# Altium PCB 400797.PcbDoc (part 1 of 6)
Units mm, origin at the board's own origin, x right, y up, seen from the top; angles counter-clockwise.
Board outline 155 x 63.5 mm, 4 copper layers (Top Layer, Mid-Layer 1, Mid-Layer 2, Bottom Layer), stack 1.514 mm thick; 317 components, 286 nets, 1519 pads, 2174 vias.
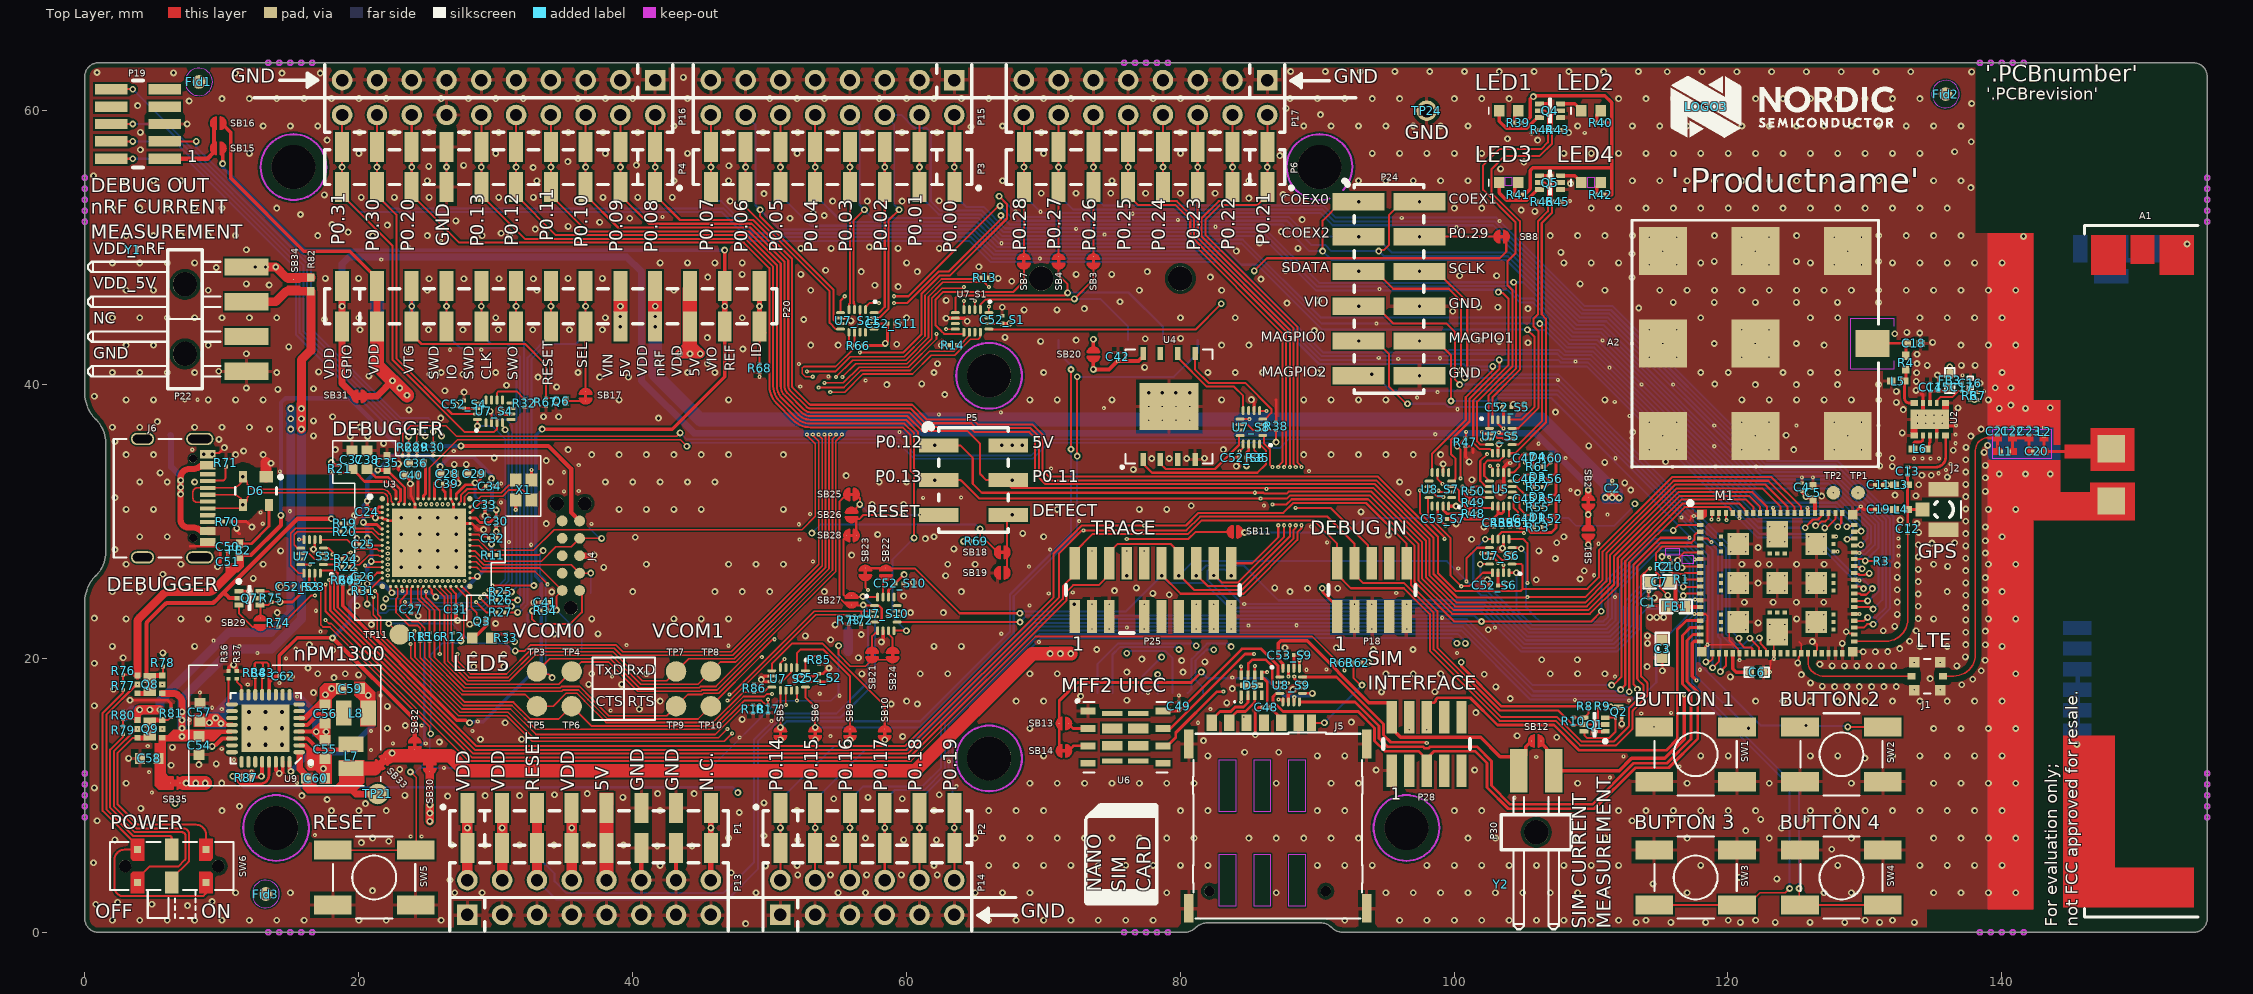
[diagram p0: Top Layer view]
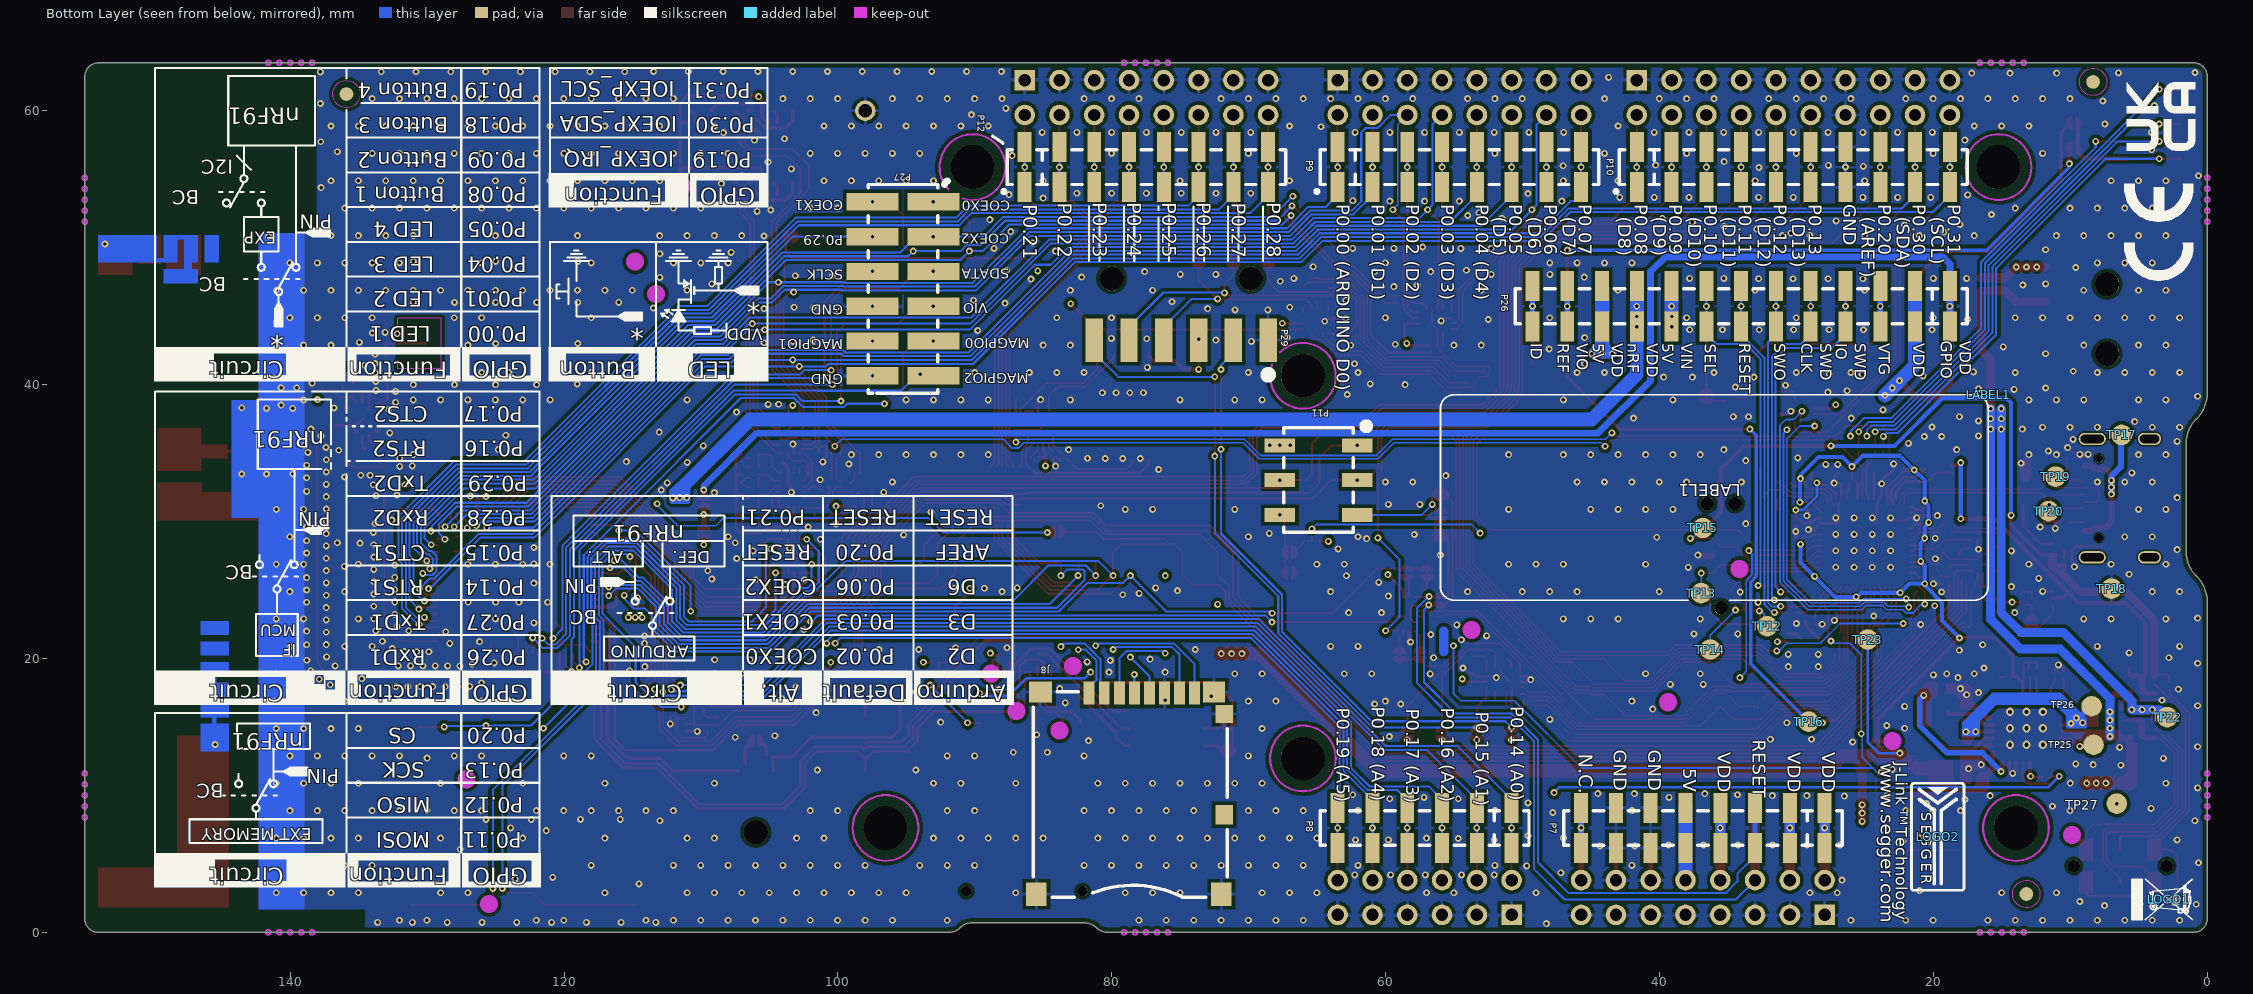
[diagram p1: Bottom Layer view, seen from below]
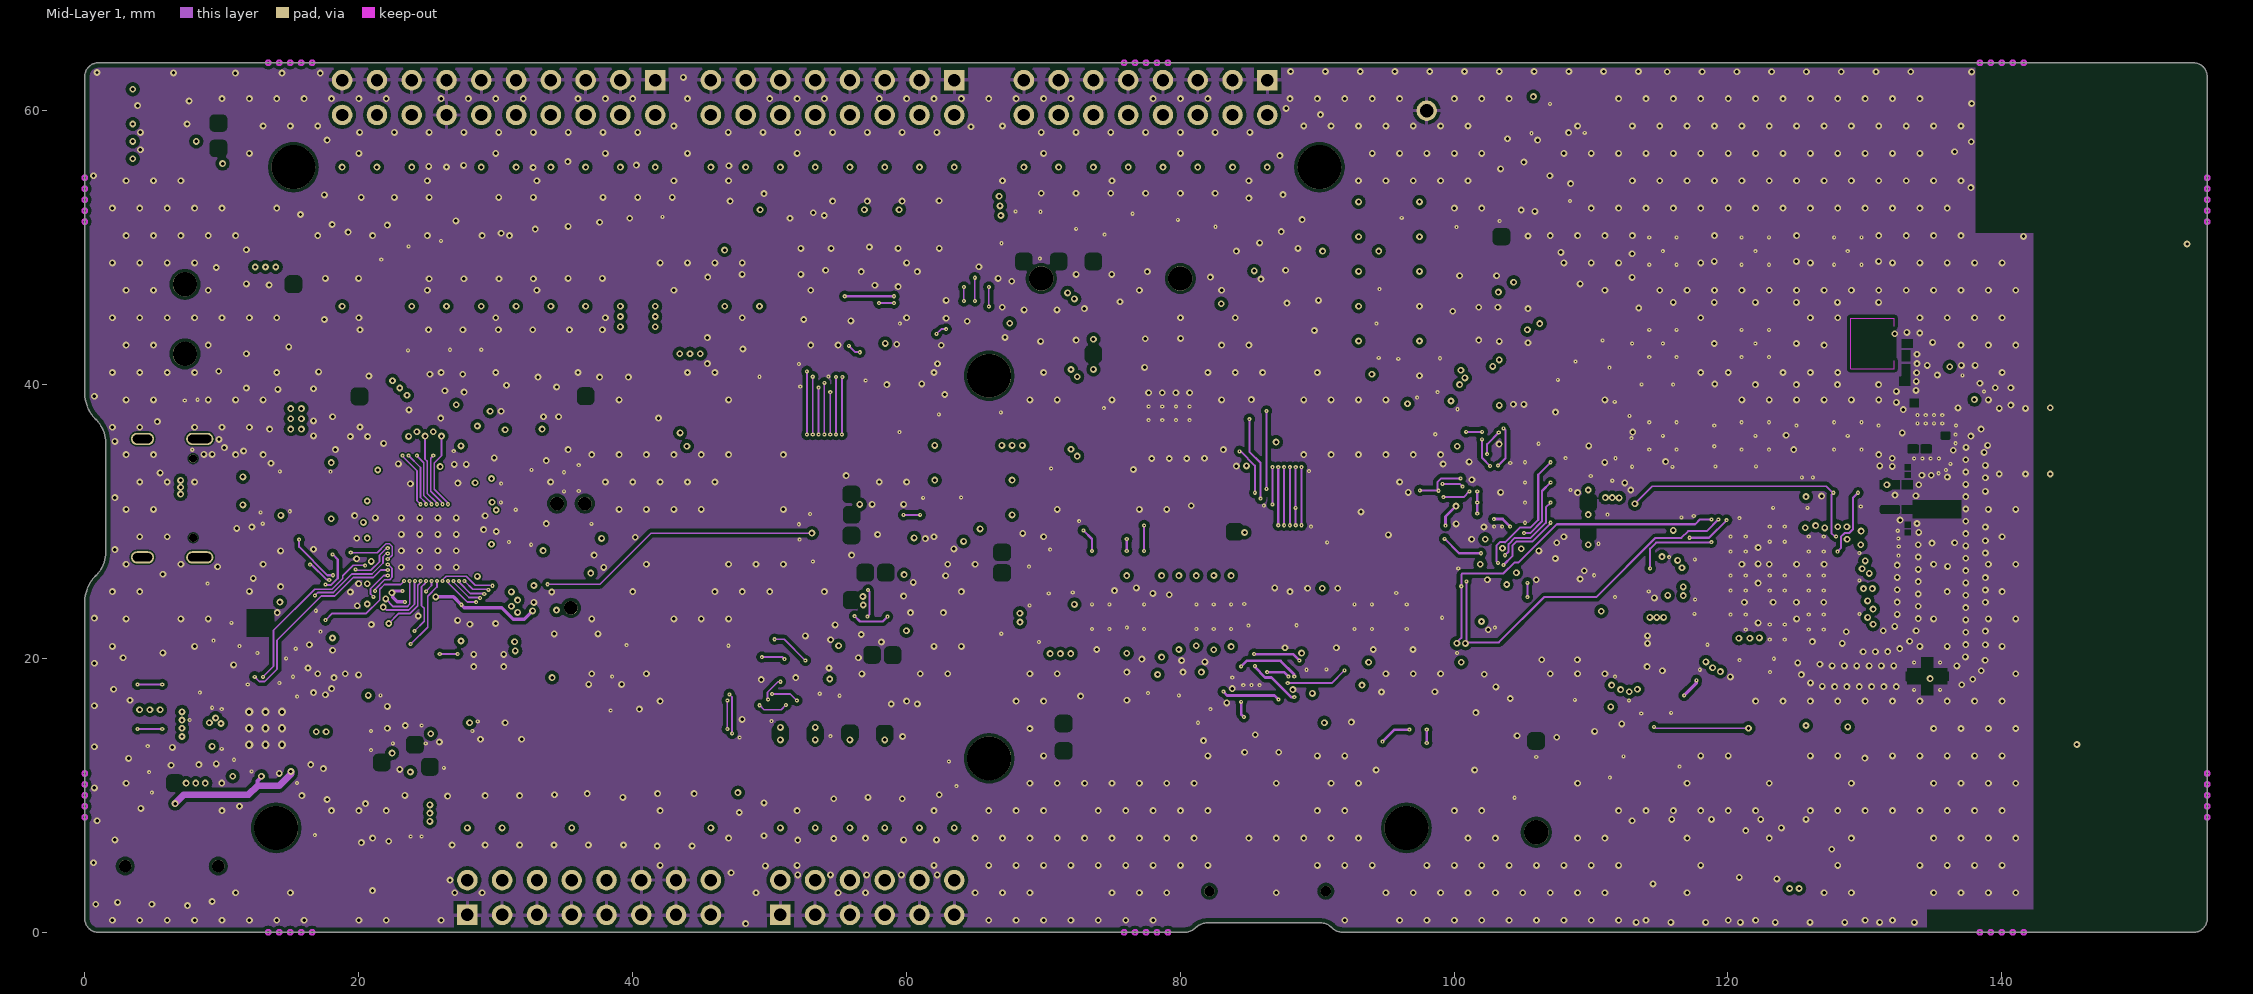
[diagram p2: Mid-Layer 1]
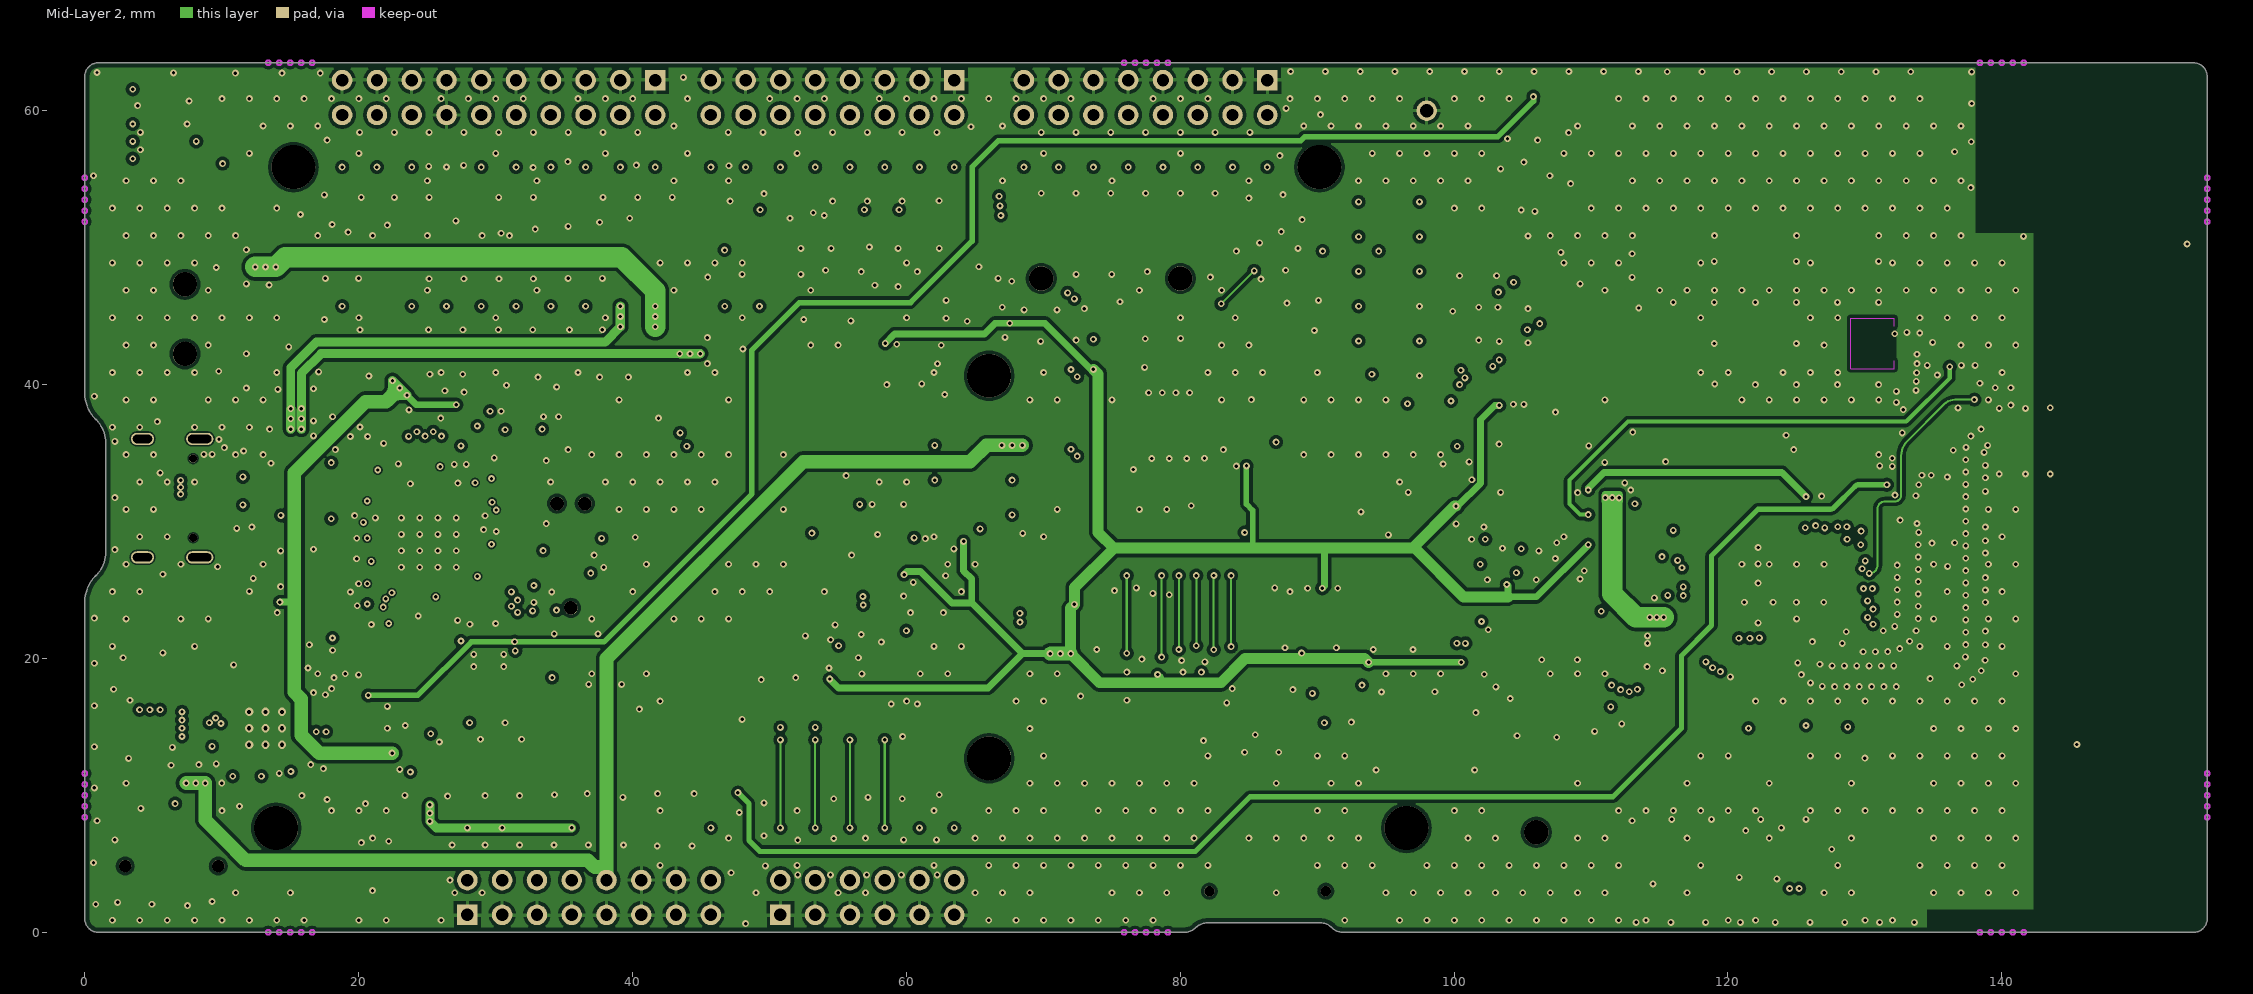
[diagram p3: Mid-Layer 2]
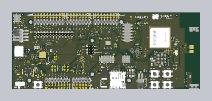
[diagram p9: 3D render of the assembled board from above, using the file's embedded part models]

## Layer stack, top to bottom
Top Solder: solder mask 0.05, Solder Resist Halogen-Free, Dk 3.5
Top Layer: signal copper 0.035
Dielectric1: prepreg 0.072, FR-4 Halogen-Free, Dk 4.18
Mid-Layer 1: signal copper 0.035
Dielectric2: core 1.23, FR-4 Halogen-Free, Dk 4.74
Mid-Layer 2: signal copper 0.035
Dielectric3: prepreg 0.072, FR-4 Halogen-Free, Dk 4.18
Bottom Layer: signal copper 0.035
Bottom Solder: solder mask 0.05, Solder Resist Halogen-Free, Dk 3.5

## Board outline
0,1 0,24.121 cw(c2.717,24.121) 0.796,26.042 0.962,26.208 ccw(c-0.876,27.751) 1.524,27.751 1.524,35.751 ccw(c-0.876,35.751) 0.962,37.294 0.796,37.46 cw(c2.717,39.381) 0,39.381 0,62.5 cw(c1,62.5) 1,63.5 154,63.5 cw(c154,62.5) 155,62.5 155,1 cw(c154,1) 154,0 91.9,0 cw(c91.9,1.18) 91.066,0.346 ccw(c90.231,-0.489) 90.231,0.691 81.969,0.691 ccw(c81.969,-0.489) 81.134,0.346 cw(c80.3,1.18) 80.3,0 1,0 cw(c1,1)

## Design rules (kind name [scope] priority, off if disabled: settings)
BoardOutlineClearance [OnLayer('Top Layer') or OnLayer('Bottom Layer') or OnLayer('Mid-Layer 1') or OnLayer('Mid-Layer 2')] p1: gap=0.35 ignorepadtopadclearanceinfootprint=FALSE
Clearance USB_C [InComponent('J6')] p1: gap=0.1 ignorepadtopadclearanceinfootprint=FALSE
Clearance IMCU_room [WithinRoom('IMCU')] p2: gap=0.1 ignorepadtopadclearanceinfootprint=FALSE
Clearance USB_Poly_Clearance [(InNamedPolygon('Top_Layer-GND')) vs (IsTrack or IsArc) and (InDifferentialPair('D') or InDifferentialPair('USB0'))] p3: gap=1 ignorepadtopadclearanceinfootprint=FALSE
Clearance "NPTH clearance" [Not PadIsPlated And HoleSize > 0] p4: gap=0.23 ignorepadtopadclearanceinfootprint=FALSE
Clearance SB_Clearance [HasFootprint('Solderbridge') or HasFootprint('QFN40P180X140X55-10N')] p5: gap=0.127 ignorepadtopadclearanceinfootprint=FALSE except(0: Arc-Hole Track-Hole SMDPad-Hole THPad-Hole Via-Hole Fill-Hole Poly-Hole Region-Hole Text-Hole)
Clearance CSP_Clearance [HasFootprint('BGA4C40P2X2_76X76X62')] p6: gap=0.127 ignorepadtopadclearanceinfootprint=FALSE except(0: Arc-Hole Track-Hole SMDPad-Hole THPad-Hole Via-Hole Fill-Hole Poly-Hole Region-Hole Text-Hole)
Clearance P23_Clearance [HasFootprint('FPC_05P-0.5mm-RA-SMD')] p7: gap=0.127 ignorepadtopadclearanceinfootprint=FALSE except(0: Arc-Hole Track-Hole SMDPad-Hole THPad-Hole Via-Hole Fill-Hole Poly-Hole Region-Hole Text-Hole)
Clearance PSON35P100X50-8N_Clearance [HasFootprint('PSON35P100X50-8N')] p8: gap=0.15 ignorepadtopadclearanceinfootprint=FALSE except(0: Arc-Hole Track-Hole SMDPad-Hole THPad-Hole Via-Hole Fill-Hole Poly-Hole Region-Hole Text-Hole)
Clearance "Net tie_clearance" [InComponent('NT*') vs IsPad] p9: gap=0.001 ignorepadtopadclearanceinfootprint=TRUE
Clearance Top_layer_Clearance [All vs OnLayer('Top Layer')] p10: gap=0.125 ignorepadtopadclearanceinfootprint=FALSE
Clearance Polygon_Clearance [InNamedPolygon('Top_Layer-GND') or InNamedPolygon('Bottom_Layer-GND') or InNamedPolygon('Mid_Layer_1-GND') or InNamedPolygon('Mid_Layer_2-GND')] p11: gap=0.25 ignorepadtopadclearanceinfootprint=FALSE except(0: Arc-Hole Track-Hole SMDPad-Hole THPad-Hole Via-Hole Fill-Hole Poly-Hole Region-Hole Text-Hole)
Clearance USB_Clearance [InDifferentialPairClass('All Differential Pairs')] p12: gap=0.15 ignorepadtopadclearanceinfootprint=FALSE
Clearance RF_Clerance [InNet('RF') or InNet('ANT')] p13: gap=0.203 ignorepadtopadclearanceinfootprint=FALSE except(0: Arc-Hole Track-Hole SMDPad-Hole THPad-Hole Via-Hole Fill-Hole Poly-Hole Region-Hole Text-Hole)
Clearance [All] p14: gap=0.125 ignorepadtopadclearanceinfootprint=FALSE except(0: Poly-Region Region-Region)
ComponentClearance [All] p1 off: gap=0.254 collisioncheckmode=3 verticalgap=0.254 showdistances=FALSE
DiffPairsRouting [InDifferentialPair('D')] p1: maxlimit=0.15 minlimit=0.127 mostfreqgap=0.15 toplayer_mingap=0.15 toplayer_minwidth=0.1 toplayer_maxwidth=0.1 toplayer_prefwidth=0.1 midlayer1_maxgap=0.127 midlayer1_prefgap=0.127 midlayer1_minwidth=0.054 midlayer1_maxwidth=0.054 midlayer1_prefwidth=0.054 midlayer2_maxgap=0.127 midlayer2_prefgap=0.127 midlayer2_minwidth=0.054 midlayer2_maxwidth=0.054 midlayer2_prefwidth=0.054 bottomlayer_mingap=0.15 bottomlayer_minwidth=0.1 bottomlayer_maxwidth=0.1 bottomlayer_prefwidth=0.1 impedanceprofiledriven=TRUE impedanceprofileid={5F1D737F-A6A0-4321-8E3C-81C77A155CAF} impedanceprofilevalue=90.000000 maxuncoupledlength=12.7
FabricationTestPointUsage TestPointUsage [All] p1: valid=0 allowmultiple=FALSE
FabricationTestpoint Testpoint [All] p1: side=3 testpointundercomponent=TRUE minsize=1.016 maxsize=2.54 preferedsize=1.524 minholesize=0 maxholesize=1.016 preferedholesize=0.813 testpointgrid=0.025 allowsidetop=TRUE allowsidebottom=TRUE usegrid=TRUE gridtolerance=0
Height [All] p1 off: minheight=0 maxheight=25.4 prefheight=12.7
HoleSize [All] p1: absolutevalues=TRUE maxlimit=5 minlimit=0.1 maxpercent=80.000 minpercent=20.000
HoleToHoleClearance [All] p1: gap=0.25 allowstackedmicrovias=FALSE
MinimumAnnularRing [All] p1 off: minimumring=0.152
MinimumSolderMaskSliver USB-C [HasFootprint('SD-80259-001')] p1: minsoldermaskwidth=0
MinimumSolderMaskSliver PMIC [WithinRoom('nPM1300')] p2: minsoldermaskwidth=0
MinimumSolderMaskSliver [All] p3: minsoldermaskwidth=0.05
NetAntennae NetAntennae_ANT [InNet('ANT')] p1: netantennaetolerance=40
NetAntennae [All] p2: netantennaetolerance=0
PlaneClearance [All] p1: clearance=0.25
PlaneConnect [All] p1: planeconnectstyle=Direct reliefexpansion=0.508 reliefentries=4 reliefconductorwidth=0.254 reliefairgap=0.254
PolygonConnect VDD_nRF [InNet('VDD_nRF')] p1: connectstyle=Direct reliefconductorwidth=0.254 reliefentries=4 polygonreliefangle="90 Angle" airgapwidth=0.254
PolygonConnect VCC_and_VDD [InNet('NetC50_2')] p2: connectstyle=Direct reliefconductorwidth=0.254 reliefentries=4 polygonreliefangle="90 Angle" airgapwidth=0.254
PolygonConnect GND_Poly [isVia and innet(gnd) or isVia and innet('VDD') or HasFootprint('COAXIAL-SWF') or isVia and innet('VDD_SAM') or InComponent('R80') or HasFootprint('COAXIAL RF U.FL-R-SMT-1') or HasFootprint('DSGP.1575.18') or HasFootprint('DX07S016JA1R1500')] p3: connectstyle=Direct reliefconductorwidth=0.254 reliefentries=4 polygonreliefangle="90 Angle" airgapwidth=0.254
PolygonConnect General [All] p4: connectstyle=Relief reliefconductorwidth=0.254 reliefentries=4 polygonreliefangle="90 Angle" airgapwidth=0.254
RoomDefinition IMCU [InComponentClass('IMCU') vs False] p1: confinementstyle=ConfineIn formatcopy=TRUE lockcomponents=FALSE outline 18.089,33.044 18.089,34.657 18.67,34.657 18.67,36.019 21.455,36.019 21.455,35.514 22.755,35.514 22.755,34.944 25.405,34.944 25.405,34.164 27.705,34.164 29.68,34.164 29.68,33.844 33.38,33.844 33.38,30.783 30.586,30.783 30.586,29.228 30.582,29.228 30.582,28.248 28.954,28.248 28.954,24.43 27.636,24.43 27.636,22.778 24.279,22.778 24.279,20.471 21.721,20.471 21.721,24.43 20.321,24.43 20.321,25.423 19.543,25.423 19.543,27.798 19.543,33.009 18.67,33.009 18.67,33.044
RoomDefinition nPM1300 [InComponentClass('nPM1300') vs False] p2: confinementstyle=ConfineIn formatcopy=TRUE lockcomponents=FALSE outline 5.325,8.12 5.325,10.678 7.021,10.678 7.021,17.679 9.846,17.679 9.846,18.254 9.966,18.254 9.966,19.604 19.196,19.604 19.196,39.954 21.104,39.954 21.104,22.659 26.074,22.659 26.074,20.101 26.049,20.101 26.049,11.145 22.974,11.145 22.974,11.124 22.654,11.124 22.654,8.846 7.883,8.846 7.883,8.12
RoutingVias [All] p1: holewidth=0.25 width=0.5 viastyle="Through Hole" minholewidth=0.1 minwidth=0.3 maxholewidth=0.305 maxwidth=0.61
ShortCircuit "PVSS and GND" [InNet('PVSS1') or InNet('PVSS2') vs InNet('GND')] p1: allowed=TRUE
ShortCircuit ShortCircuit_1 [HasFootprint('P822601')] p2: allowed=TRUE
ShortCircuit [All] p3: allowed=FALSE
SilkToSilkClearance [All] p1: silktosilkclearance=0.15
SilkToSolderMaskClearance SilkscreenOverComponentPads [IsPad] p1: minsilkscreentomaskgap=0.254 clearancetoexposedcopper=TRUE
SolderMaskExpansion SolderMaskExpansion_Via [IsVia] p1: expansion=0.102 istentingtop=TRUE
SolderMaskExpansion SolderMaskExpansion_USB [HasFootprint('L-KLS1-5473')] p2: expansion=0.06 istentingtop=FALSE
SolderMaskExpansion [All] p3: expansion=0.076 istentingtop=FALSE
UnpouredPolygon [All] p1 off:
Width Width_RF [InNet('ANT') or InNet('LTE_RF1') or InNet('GPS_RF1')] p1: maxlimit=0.254 minlimit=0.1 preferedwidth=0.254 toplayer_maxwidth=0.1 toplayer_prefwidth=0.1 bottomlayer_maxwidth=0.1 bottomlayer_prefwidth=0.1 impedanceprofiledriven=TRUE impedanceprofileid={28F3A609-7DB3-45B1-BB45-39A827C1017D} impedanceprofilevalue=50.000000 minimp=50.000000 maximp=50.000000 favimp=50.000000
Width Width_Diff [(InDifferentialPairClass('All Differential Pairs'))] p2: maxlimit=0.165 minlimit=0.1 preferedwidth=0.165
Width Width_GPIO [InNetClass('GPIO')] p3: maxlimit=0.152 minlimit=0.125 preferedwidth=0.15 minimp=50.000000 maximp=50.000000 favimp=50.000000
Width Width_GPIO_1 [InNetClass('COEX')] p4: maxlimit=0.152 minlimit=0.125 preferedwidth=0.15 minimp=50.000000 maximp=50.000000 favimp=50.000000
Width Width_GPIO_2 [InNetClass('SWD')] p5: maxlimit=0.152 minlimit=0.125 preferedwidth=0.15 minimp=50.000000 maximp=50.000000 favimp=50.000000
Width Width_GPIO_3 [InNetClass('UART')] p6: maxlimit=0.152 minlimit=0.125 preferedwidth=0.15 minimp=50.000000 maximp=50.000000 favimp=50.000000
Width [All] p7: maxlimit=2.54 minlimit=0.125 preferedwidth=0.15
15 further rules are at their usual default settings.

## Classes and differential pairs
net class VCOM: VCOM0_CTRL VCOM0_CTS VCOM0_HWFC VCOM0_RTS VCOM0_RXD VCOM0_TXD VCOM1_CTRL VCOM1_CTS VCOM1_HWFC VCOM1_RTS VCOM1_RXD VCOM1_TXD
net class nRF9151_UART: P0.14/AIN1 P0.15/AIN2 P0.16/AIN3 P0.17/AIN4 P0.26 P0.27 P0.28 P0.29
net class EXT_MEM: P0.11 P0.12 P0.13/AIN0 P0.20/AIN7
component class IMCU: C24 C25 C26 C27 C28 C29 C30 C31 C32 C33 C34 C35 C36 C37 C38 C39 C40 R21 TP11 U3 X1
component class nPM1300: C54 C55 C56 C57 C59 C60 C62 L7 L8 R36 R37 R87 SB30 SB31 SB32 SB33 TP21 TP23 TP25 TP26 TP27 U9
net class RF: ANT GPS_RF1 GPS_RF2 GPS_RF3 GPS_RF4 GPS_RF5 LTE_RF1 NetA1_1 NetC20_1
channel class pca10171_switch_nx: S7 S9
channel class pca10171_switch_fsa: S1 S2 S3 S4 S5 S6 S8 S10 S11
net class SWD: P0.22 RESET SWD0_CLK SWD0_IO SWD0_RESET SWD0_SEL SWD0_SWO SWD1_CLK SWD1_IO SWD1_RESET SWD1_SEL SWD1_SWO SWD3_CLK SWD3_IO SWD3_RESET SWD3_SWO SWD_CTRL SWDCLK SWDIO
net class COEX: COEX0 COEX1 COEX2 MAGPIO0 MAGPIO1 MAGPIO2 MIPI_SCLK MIPI_SDATA MIPI_VIO
net class GPIO: AREF BTN1_EXT BTN2_EXT BTN3_EXT BTN4_EXT BUTTON1 BUTTON2 BUTTON3 BUTTON4 COEX0 COEX1 COEX2 COEX_SELECT COM.CH1_S1 COM.CH2_S2 COM.CH3_S1 COM.CH4_S2 EXT_MEM_C\S\ EXT_MEM_CTRL EXT_MEM_MISO EXT_MEM_MOSI EXT_MEM_SCK IMCU_LED IMCU_SCL IMCU_SDA INT_EXT IOEXP_CTRL LED1 LED1_EXT LED2 LED2_EXT LED3 LED3_EXT LED4 LED4_EXT MAGPIO0 MAGPIO1 MAGPIO2 MIPI_SCLK MIPI_SDATA MIPI_VIO NC.CH1_S3 NC.CH3_S3 NC.CH4_S3 NetC44_1 NetC45_2 NetC46_2 NetC47_2 NetR51_1 NetR58_1 NO.CH1_S8 P0.00 P0.01 P0.02 P0.03 P0.04 P0.05 P0.06 P0.07 P0.08 P0.09 P0.10 P0.11 P0.12 P0.13/AIN0 P0.14/AIN1 P0.15/AIN2 P0.16/AIN3 P0.17/AIN4 P0.18/AIN5 P0.19/AIN6 P0.20/AIN7 P0.21 P0.22 P0.23 P0.24 P0.25 P0.26 P0.27 P0.28 P0.29 P0.30 P0.31 RESET RESET_BUTTON RESET_IN_CTRL RESET_OUT_CTRL SCL_EXT SDA_EXT SHIELD_DETECT SIM_SELECT SWD0_CLK SWD0_IO SWD0_RESET SWD0_SEL SWD0_SWO SWD1_CLK SWD1_IO SWD1_RESET SWD1_SEL SWD1_SWO SWD3_CLK SWD3_IO SWD3_RESET SWD3_SWO SWD_CTRL SWDCLK SWDIO TGT_SCL TGT_SDA TGT_TWI_CTRL UART1.CTS UART1.RTS UART1.RXD UART1.TXD UART2.CTS UART2.RTS UART2.RXD UART2.TXD USB_DETECT VCOM0_CTRL VCOM0_CTS VCOM0_HWFC VCOM0_RTS VCOM0_RXD VCOM0_TXD VCOM1_CTRL VCOM1_CTS VCOM1_HWFC VCOM1_RTS VCOM1_RXD VCOM1_TXD VIO_REF_SENSE
differential pair D: +D_P -D_N

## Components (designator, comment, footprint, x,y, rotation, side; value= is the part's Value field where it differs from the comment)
A1 "P822601" P822601 150.28,26.417 r270 top
A2 "DSGP.1575.18" DSGP.1575.18.4.C.02 122,43 r90 top
C1 "1.0µF" CAPC0603X03L_C 114.19,24.1 r90 top value=1.0ÂµF
C2 "1.0µF" CAPC0603X03L_C 111.55,32.425 r90 top value=1.0ÂµF
C3 "10µF" CAPC1608X06L 115.2,20.7 r270 top value=10ÂµF
C4 "100nF" CAPC0603X03L_C 125.4,32.5 r90 top
C5 "4.7µF" CAPC1005X04L 126.2,32.1 r90 top value=4.7ÂµF
C6 "4.7µF" CAPC1005X04L 122.1,19 r0 top value=4.7ÂµF
C7 "10µF" CAPC1608X06L 115,25.6 r180 top value=10ÂµF
C10 "100nF" CAPC0603X03L_C 115.8,26.7 r90 top
C11 "39pF" CAPC0603X03L_C 131.03,32.68 r0 top
C12 "39pF" CAPC0603X03L_C 133.13,29.48 r270 top
C13 "39pF" CAPC0603X03L_C 133.13,33.682 r270 top
C14 "100pF" CAPC0603X03L_C 134.8,39.822 r270 top
C15 "100nF" CAPC0603X03L_C 135.375,39.822 r270 top
C16 "100nF" CAPC0603X03L_C 137.7,40.1 r270 top
C17 "100pF" CAPC0603X03L_C 137.1,39.8 r270 top
C18 "N.C." CAPC1005X04L_NC 133.575,43 r0 top
C19 "N.C." CAPC0603X03L_C_NC 131.03,30.88 r0 top
C20 "3.5pF" CAPC0603X03L_C 142.545,35.117 r0 top
C21 "N.C." CAPC0603X03L_C_NC 139.7,36.577 r270 top
C22 "N.C." CAPC0603X03L_C_NC 140.784,36.577 r270 top
C23 "N.C." CAPC0603X03L_C_NC 141.986,36.577 r270 top
C24 "100nF" CAPC0603X03L_C 20.625,30.709 r90 top
C25 "100nF" CAPC0603X03L_C 20.35,28.334 r0 top
C26 "100nF" CAPC0603X03L_C 20.35,25.959 r180 top
C27 "100nF" CAPC0603X03L_C 23.827,23.584 r90 top
C28 "1.0µF" CAPC1005X04L 26.475,33.484 r0 top value=1.0ÂµF
C29 "1.0µF" CAPC1005X04L 28.45,33.484 r0 top value=1.0ÂµF
C30 "2.2nF" CAPC0603X03L_C 30.05,30.034 r270 top
C31 "100nF" CAPC0603X03L_C 27.1,23.584 r90 top
C32 "100nF" CAPC0603X03L_C 29.775,28.784 r180 top
C33 "100nF" CAPC0603X03L_C 29.225,31.234 r90 top
C34 "100nF" CAPC0603X03L_C 29.575,32.575 r0 top
C35 "1.0µF" CAPC1005X04L 22.075,34.284 r270 top value=1.0ÂµF
C36 "1.0µF" CAPC1005X04L 24.175,34.264 r0 top value=1.0ÂµF
C37 "4.7µF" CAPC1608X06L 19.5,34.514 r90 top value=4.7ÂµF
C38 "4.7µF" CAPC1608X06L 20.625,34.514 r90 top value=4.7ÂµF
C39 "100nF" CAPC0603X03L_C 26.444,32.759 r0 top
C40 "1.0µF" CAPC1005X04L 23.825,33.389 r0 top value=1.0ÂµF
C41 "10nF" CAPC0603X03L_C 33.625,24.1 r0 top
C42 "100nF" CAPC0603X03L_C 75.45,42.05 r270 top
C43 "100nF" CAPC0603X03L_C 102.927,29.912 r90 top
C44 "1.0µF" CAPC0603X03L_C 105.174,30.191 r270 top value=1.0ÂµF
C45 "1.0µF" CAPC0603X03L_C 105.174,31.664 r90 top value=1.0ÂµF
C46 "1.0µF" CAPC0603X03L_C 105.174,33.137 r90 top value=1.0ÂµF
C47 "1.0µF" CAPC0603X03L_C 105.174,34.611 r90 top value=1.0ÂµF
C48 "10nF" CAPC0603X03L_C 86.275,16.425 r180 top
C49 "N.C." CAPC0603X03L_C_NC 79.9,16.5 r270 top
C50 "10nF" CAPC0603X03L_C 10.425,28.15 r90 top
C51 "100nF" CAPC0603X03L_C 10.425,27.05 r270 top
C52_S1 "100nF" CAPC0603X03L_C 67,44.75 r90 top (schematic designator C52)
C52_S2 "100nF" CAPC0603X03L_C 53.625,18.6 r90 top (schematic designator C52)
C52_S3 "100nF" CAPC0603X03L_C 15.55,25.25 r180 top (schematic designator C52)
C52_S4 "100nF" CAPC0603X03L_C 27.7,38.55 r90 top (schematic designator C52)
C52_S5 "100nF" CAPC0603X03L_C 103.898,38.359 r0 top (schematic designator C52)
C52_S6 "100nF" CAPC0603X03L_C 102.923,25.334 r180 top (schematic designator C52)
C52_S8 "100nF" CAPC0603X03L_C 84.553,34.671 r180 top (schematic designator C52)
C52_S10 "100nF" CAPC0603X03L_C 59.5,25.475 r0 top (schematic designator C52)
C52_S11 "100nF" CAPC0603X03L_C 58.9,44.45 r0 top (schematic designator C52)
C53_S7 "100nF" CAPC0603X03L_C 99.197,30.192 r0 top (schematic designator C53)
C53_S9 "100nF" CAPC0603X03L_C 88,20.25 r180 top (schematic designator C53)
C54 "1.0µF" CAPC1608X06L 8.35,13.65 r90 top value=1.0ÂµF
C55 "10µF" CAPC1608X06L 17.55,13.35 r90 top value=10ÂµF
C56 "10µF" CAPC1608X06L 17.55,15.95 r270 top value=10ÂµF
C57 "10µF" CAPC1608X06L 8.4,16.075 r270 top value=10ÂµF
C58 "4.7µF" CAPC1608X06L 4.7,12.7 r0 top value=4.7ÂµF
C59 "10µF" CAPC1608X06L 19.4,17.8 r0 top value=10ÂµF
C60 "10µF" CAPC1608X06L 16.85,11.25 r180 top value=10ÂµF
C62 "100nF" CAPC0603X03L_C 14.5,18.7 r0 top
D1 "CFSH05-20L" SODFL35X40-2N 106.114,30.318 r180 top
D2 "CFSH05-20L" SODFL35X40-2N 106.114,31.791 r180 top
D3 "CFSH05-20L" SODFL35X40-2N 106.114,33.264 r180 top
D4 "CFSH05-20L" SODFL35X40-2N 106.114,34.738 r180 top
D5 "TPD3F303DPVR" SON50P210X160X65_HS-9N 85.2,18.05 r90 top
D6 "PRTR5V0U2X" SOT190P230X110-4L 12.497,32.234 r270 top
FB1 "22R@100M/6A" INDC1608X06L 116.2,23.8 r0 top
FB2 "120R/0.55A" INDC1005X04L 11.3,27.9 r270 top
FB3 "120R/1.2A" INDC1005X04L 136.2,40.3 r90 top
Fid1 "Fiducial mark" Fiducial 8.335,62.104 r0 top value=N.A.
Fid2 "Fiducial mark" Fiducial 135.89,61.214 r0 top value=N.A.
Fid3 "Fiducial mark" Fiducial 13.208,2.795 r0 top value=N.A.
J1 "MM8130-2600" COAXIAL-SWF 134.554,18.7 r90 top
J2 "MHF I Receptacle" "COAXIAL RF U.FL-R-SMT-1" 135.73,30.88 r270 top
J4 "TC2050-IDC" TC2050-IDC-NLFP 35.5,27.5 r90 top
J5 "KLS1-SIM-066" KLS1-SIM-066 82.3,15.3 r0 top
J6 "USB-C 2.0" SD-80259-001 6.6,31.705 r270 top
J8 "microSD Card Connector" Molex_502774-0891 72.75,17.55 r0 bottom
L1 "1.5nH" INDC0603X03L_C 140.233,35.117 r0 top
L2 "22nH" INDC0603X03L_C 143.084,36.573 r270 top
L3 "68nH" INDC1005X04L_WW 132.63,32.68 r0 top
L4 "N.C." INDC1005X04L_NC 132.63,30.88 r180 top
L5 "N.C." INDC1005X04L_NC 132.4,40.25 r180 top
L6 "9.1nH" INDC1005X04L_WW 134,35.3 r180 top
L7 "2.2µH" INDC2016X10N 19.45,12.85 r90 top value=2.2ÂµH
L8 "2.2µH" INDC2016X10N 19.8,16 r180 top value=2.2ÂµH
LABEL1 "15x40mm" LabelSilk_15x40 16,39.251 r0 bottom
LED1 "L0603G" LED_0603_G 104,60 r0 top
LED2 "L0603G" LED_0603_G 110,60 r0 top
LED3 "L0603G" LED_0603_G 104,54.75 r0 top
LED4 "L0603G" LED_0603_G 110,54.75 r0 top
LED5 "L0603G" LED_0603_G 29,21.5 r0 top
LOGO1 "WEE Symbol" WEE_3x4.5mm 2.8,2.4 r270 bottom
LOGO2 "Segger Logo S" SEGGER_LOGO_S 19.675,6.975 r270 bottom
LOGO3 "Nordic Logo" NORDIC_LOGO_LYING 118.4,60.275 r0 top
M1 "nRF9151-LACAA0A" LGA50P1210X1110X130-113N 123.6,25.5 r270 top
P1 "Socket 1x8" SOCKET_1x8_SMD 27.94,7.621 r0 top
P2 "Socket 1x6" SOCKET_1x6_SMD 50.8,7.621 r0 top
P3 "Socket 1x8" SOCKET_1x8_SMD 63.5,55.881 r180 top
P4 "Socket 1x10" SOCKET_1x10_SMD 41.656,55.881 r180 top
P5 "Pin Hdr 2x3" HDR_2x3-SMD 64.897,33.021 r270 top
P6 "Socket 1x8" SOCKET_1x8_SMD 86.36,55.881 r180 top
P7 "Pin List 1x8" LIST_1x8_SMD-NC 27.94,7.621 r0 bottom
P8 "Pin List 1x6" LIST_1x6_SMD-NC 50.8,7.621 r0 bottom
P9 "Pin List 1x8" LIST_1x8_SMD-NC 63.5,55.881 r180 bottom
P10 "Pin List 1x10" LIST_1x10_SMD-NC 41.656,55.881 r180 bottom
P11 "Socket 2x3" SOCKET_2x3_SMD-2.54mm-bottom-NC 64.897,33.021 r270 top
P12 "Pin List 1x8" LIST_1x8_SMD-NC 86.36,55.881 r180 bottom
P13 "Pin Header 2x8" HDR_2x8-NC 36.83,2.541 r0 top
P14 "Pin Header 2x6" HDR_2x6-NC 57.15,2.541 r0 top
P15 "Pin Header 2x8" HDR_2x8-NC 54.61,60.961 r180 top
P16 "Pin Header 2x10" HDR_2x10-NC 30.226,60.961 r180 top
P17 "Pin Header 2x8" HDR_2x8-NC 77.47,60.961 r180 top
P18 "Pin Header 2x5, 1.27mm" HDR_2x5-SMD-1.27mm-K 94,25 r0 top
P19 "Pin Header 2x5, 1.27mm" HDR_2x5-SMD-1.27mm-K 3.886,59.031 r90 top
P20 "Pin List 1x13" LIST_1x13_SMD 18.796,45.721 r0 top
P22 "Pin List 1x4, Angled" LIST_ANG_1x4-SMD-2.54MM 11.811,44.779 r270 top
P24 "Socket 2x6" SOCKET_2x6_SMD-2.54mm#1 95.25,46.991 r270 top
P25 "Pin Header 2x10, 1.27mm, SWD" HDR_2x10-SMD-1.27mm-K-SWD 78,25 r0 top
P26 "Socket 1x13" LIST_1x13_SMD-NC 18.796,45.721 r0 bottom
P27 "Socket 2x6" SOCKET_2x6_SMD-2.54mm#2 95.25,46.991 r270 bottom
P28 "Pin Header 2x5, 1.27mm" HDR_2x5-SMD-1.27mm 98,13.75 r0 top
P29 "Pin List 1x6, Angled" LIST_ANG_1x6-SMD-2.54MM 74.93,43.25 r0 bottom
P30 "Pin List 1x2, Angled" LIST_ANG_1x2-SMD-2.54MM 106,11.8 r0 top
Q1 "DMC2400UV" SOTFL50P162X60-6N 110.265,15.175 r180 top
Q2 "RV2C010UNT2L" DFN65P100X40-3L 112.015,16.1 r90 top
Q3 "RV2C010UNT2L" DFN65P100X40-3L 28.975,22.725 r0 top
Q4 "UM6X1NA" SOTFL50P162X60-6N 107,60 r180 top
Q5 "UM6X1NA" SOTFL50P162X60-6N 107,54.75 r180 top
Q6 "RV2C010UNT2L" DFN65P100X40-3L 34.775,38.8 r0 top
Q7 "DMC2400UV" SOTFL50P162X60-6N 12.025,24.4 r0 top
Q8 "MCM2301" DFN65P200X200X80_HS-6N 4.75,18.1 r0 top
Q9 "MCM2301" DFN65P200X200X80_HS-6N 4.75,14.85 r0 top
R1 "10k" RESC0603X03L_C 116.6,25.8 r0 top
R2 "1k" RESC0603X03L_C 115.2,26.7 r270 top
R3 "1M0" RESC0603X03L_C 131.2,27.1 r180 top
R4 "0R" RESC1005X04L 133,41.6 r90 top
R6 "1k" RESC0603X03L_C 137.675,39.172 r90 top
R7 "1M0" RESC0603X03L_C 138.25,39.172 r270 top
R8 "10k" RESC0603X03L_C 109.54,16.5 r0 top
R9 "N.C." RESC0603X03L_C_NC 110.815,16.5 r0 top
R10 "100k" RESC0603X03L_C 108.715,15.4 r90 top
R11 "150R" RESC0603X03L_C 29.775,27.55 r0 top
R12 "150R" RESC0603X03L_C 26.85,21.584 r270 top
R13 "1M0" RESC0603X03L_C 65.725,47.8 r0 top
R14 "1M0" RESC0603X03L_C 63.4,42.875 r0 top
R15 "150R" RESC0603X03L_C 24.5,21.584 r270 top
R16 "150R" RESC0603X03L_C 25.175,21.584 r270 top
R17 "1M0" RESC0603X03L_C 49.9,16.3 r270 top
R18 "1M0" RESC0603X03L_C 48.8,16.3 r90 top
R19 "150R" RESC0603X03L_C 18.975,29.859 r180 top
R20 "150R" RESC0603X03L_C 18.975,29.259 r180 top
R21 "2R2" RESC0603X03L_C 18.625,33.85 r270 top
R22 "150R" RESC0603X03L_C 19.075,26.684 r180 top
R23 "N.C." RESC0603X03L_C_NC 16.675,25.25 r180 top
R24 "1M0" RESC0603X03L_C 19.075,27.275 r180 top
R25 "150R" RESC0603X03L_C 30.375,24.859 r0 top
R26 "150R" RESC0603X03L_C 30.375,24.259 r0 top
R27 "150R" RESC0603X03L_C 30.375,23.359 r0 top
R28 "150R" RESC0603X03L_C 23.65,35.409 r90 top
R29 "150R" RESC0603X03L_C 24.25,35.409 r90 top
R30 "150R" RESC0603X03L_C 25.45,35.409 r90 top
R31 "1M0" RESC0603X03L_C 20.35,24.925 r180 top
R32 "1M0" RESC0603X03L_C 32.1,38.65 r90 top
R33 "120R" RESC0603X03L_C 30.75,21.5 r270 top
R34 "100k" RESC0603X03L_C 33.625,23.5 r180 top
R35 "100k" RESC0603X03L_C 85.653,34.671 r180 top
R36 "47k" RESC0603X03L_C 10.5,18.8 r90 top
R37 "150k" RESC0603X03L_C 11.1,18.8 r90 top
R38 "1M0" RESC0603X03L_C 87.003,36.946 r270 top
R39 "120R" RESC0603X03L_C 104.699,59.118 r0 top
R40 "120R" RESC0603X03L_C 110.699,59.118 r0 top
R41 "120R" RESC0603X03L_C 104.699,53.868 r0 top
R42 "120R" RESC0603X03L_C 110.699,53.868 r0 top
R43 "1M0" RESC0603X03L_C 107.574,58.6 r180 top
R44 "1M0" RESC0603X03L_C 106.456,58.6 r0 top
R45 "1M0" RESC0603X03L_C 107.563,53.35 r180 top
R46 "1M0" RESC0603X03L_C 106.445,53.35 r0 top
R47 "1M0" RESC0603X03L_C 100.825,35.775 r90 top
R48 "4k7" RESC0603X03L_C 101.403,30.572 r0 top
R49 "4k7" RESC0603X03L_C 101.403,31.385 r0 top
R50 "12k" RESC0603X03L_C 101.403,32.198 r0 top
R51 "12k" RESC0603X03L_C 104.68,29.912 r270 top
R52 "100k" RESC0603X03L_C 107.048,30.191 r90 top
R53 "18k" RESC0603X03L_C 106.114,29.581 r0 top
R54 "100k" RESC0603X03L_C 107.048,31.664 r90 top
R55 "18k" RESC0603X03L_C 106.114,31.055 r0 top
R56 "100k" RESC0603X03L_C 107.048,33.137 r90 top
R57 "18k" RESC0603X03L_C 106.114,32.528 r0 top
R58 "0R" RESC0603X03L_C 104.095,29.912 r270 top
R59 "N.C." RESC0603X03L_C_NC 103.511,29.912 r90 top
R60 "100k" RESC0603X03L_C 107.048,34.611 r90 top
R61 "18k" RESC0603X03L_C 106.114,34.001 r0 top
R62 "1M0" RESC0603X03L_C 92.95,19.7 r180 top
R63 "100k" RESC0603X03L_C 91.8,19.7 r0 top
R64 "100k" RESC0603X03L_C 18.825,25.7 r90 top
R65 "100k" RESC0603X03L_C 19.4,25.7 r90 top
R66 "1M0" RESC0603X03L_C 56.5,42.85 r180 top
R67 "1M0" RESC0603X03L_C 33.675,38.7 r270 top
R68 "1k87" RESC0603X03L_C 49.276,41.175 r90 top
R69 "1M0" RESC0603X03L_C 65.1,28.55 r180 top
R70 "5k1" RESC0603X03L_C 10.4,30 r180 top
R71 "5k1" RESC0603X03L_C 10.3,34.3 r270 top
R72 "1M0" RESC0603X03L_C 56.7,22.8 r270 top
R73 "1M0" RESC0603X03L_C 55.775,22.8 r90 top
R74 "47k" RESC0603X03L_C 14.125,22.6 r270 top
R75 "1M0" RESC0603X03L_C 13.625,24.4 r90 top
R76 "100k" RESC0603X03L_C 2.8,19.1 r90 top
R77 "10k" RESC0603X03L_C 2.8,18 r270 top
R78 "150k" RESC0603X03L_C 5.7,19.7 r270 top
R79 "10k" RESC0603X03L_C 2.8,14.75 r90 top
R80 "1M0" RESC0603X03L_C 2.8,15.85 r90 top
R81 "100k" RESC0603X03L_C 6.3,16 r90 top
R82 "N.C." RESC1005X04L_NC 16.51,47.319 r270 top
R83 "4k7" RESC0603X03L_C 13.012,18.942 r90 top
R84 "4k7" RESC0603X03L_C 12.412,18.942 r90 top
R85 "100k" RESC0603X03L_C 53.625,19.9 r270 top
R86 "100k" RESC0603X03L_C 48.875,17.825 r90 top
R87 "0R" RESC0603X03L_C 11.8,11.3 r180 top
SB1 "Solderbridge" Solderbridge 109.8,29.2 r90 top
SB2 "Solderbridge" Solderbridge_Shorted 109.8,31.4 r270 top net-tie
SB3 "Solderbridge" Solderbridge_Shorted 73.66,49 r270 top net-tie
SB4 "Solderbridge" Solderbridge_Shorted 71.12,49 r270 top net-tie
SB5 "Solderbridge" Solderbridge_Shorted 50.8,14.5 r90 top net-tie
SB6 "Solderbridge" Solderbridge_Shorted 53.34,14.5 r90 top net-tie
SB7 "Solderbridge" Solderbridge_Shorted 68.58,49 r270 top net-tie
SB8 "Solderbridge" Solderbridge_Shorted 103.473,50.801 r0 top net-tie
SB9 "Solderbridge" Solderbridge_Shorted 55.88,14.5 r90 top net-tie
SB10 "Solderbridge" Solderbridge_Shorted 58.42,14.5 r90 top net-tie
SB11 "Solderbridge" Solderbridge 84,29.25 r0 top
SB12 "Solderbridge" Solderbridge 106,13.975 r180 top
SB13 "Solderbridge" Solderbridge 71.5,15.25 r180 top
SB14 "Solderbridge" Solderbridge_Shorted 71.5,13.25 r180 top net-tie
SB15 "Solderbridge" Solderbridge 9.75,57.25 r0 top
SB16 "Solderbridge" Solderbridge 9.75,59.095 r0 top
SB17 "Solderbridge" Solderbridge_Shorted 36.576,39.148 r90 top net-tie
SB18 "Solderbridge" Solderbridge_Shorted 67,27.75 r180 top net-tie
SB19 "Solderbridge" Solderbridge 67,26.25 r0 top
SB20 "Solderbridge" Solderbridge 73.66,42.205 r90 top
SB21 "Solderbridge" Solderbridge_Shorted 57.5,20.25 r270 top net-tie
SB22 "Solderbridge" Solderbridge 58.5,26.25 r270 top
SB23 "Solderbridge" Solderbridge_Shorted 57,26.25 r270 top net-tie
SB24 "Solderbridge" Solderbridge_Shorted 59,20.25 r270 top net-tie
SB25 "Solderbridge" Solderbridge_Shorted 56,31.981 r0 top net-tie
SB26 "Solderbridge" Solderbridge 56,30.481 r90 top
SB27 "Solderbridge" Solderbridge 56,24.25 r90 top
SB28 "Solderbridge" Solderbridge_Shorted 56,28.981 r0 top net-tie
SB29 "Solderbridge" Solderbridge 12.825,22.6 r270 top
SB30 "Solderbridge" Solderbridge_Shorted_Power 25.2,12.1 r90 top net-tie
SB31 "Solderbridge" Solderbridge_Shorted_Power 20.066,39.148 r180 top net-tie
SB32 "Solderbridge" Solderbridge_Shorted 24.1,13.7 r90 top net-tie
SB33 "Solderbridge" Solderbridge_Shorted_Power 21.7,12.4 r45 top net-tie
SB34 "Solderbridge" Solderbridge 15.24,47.319 r270 top
SB35 "Solderbridge" Solderbridge_Shorted_Power 6.6,10.9 r0 top net-tie
SW1 "PB SW" L-KLS7-TS6616B-2.5-160-T 117.64,13 r180 top
SW2 "PB SW" L-KLS7-TS6616B-2.5-160-T 128.29,13 r180 top
SW3 "PB SW" L-KLS7-TS6616B-2.5-160-T 117.64,4 r0 top
SW4 "PB SW" L-KLS7-TS6616B-2.5-160-T 128.29,4 r0 top
SW5 "PB SW" L-KLS7-TS6616B-2.5-160-T 21.136,4 r180 top
SW6 "Switch" JS102011JAQN 6.35,4.835 r0 top
TP1 "Ø1.0mm,SMD" TP_SMD_D1.0mm 129.5,32.1 r180 top value=Ã˜1.0mm,SMD
TP2 "Ø1.0mm,SMD" TP_SMD_D1.0mm 127.7,32.1 r180 top value=Ã˜1.0mm,SMD
TP3 "Ø1.5mm,SMD" TP_SMD_D1.5mm 33.02,19.05 r0 top value=Ã˜1.5mm,SMD
TP4 "Ø1.5mm,SMD" TP_SMD_D1.5mm 35.56,19.05 r0 top value=Ã˜1.5mm,SMD
TP5 "Ø1.5mm,SMD" TP_SMD_D1.5mm 33.02,16.51 r0 top value=Ã˜1.5mm,SMD
TP6 "Ø1.5mm,SMD" TP_SMD_D1.5mm 35.56,16.51 r0 top value=Ã˜1.5mm,SMD
TP7 "Ø1.5mm,SMD" TP_SMD_D1.5mm 43.18,19.05 r0 top value=Ã˜1.5mm,SMD
TP8 "Ø1.5mm,SMD" TP_SMD_D1.5mm 45.72,19.05 r0 top value=Ã˜1.5mm,SMD
TP9 "Ø1.5mm,SMD" TP_SMD_D1.5mm 43.18,16.51 r0 top value=Ã˜1.5mm,SMD
TP10 "Ø1.5mm,SMD" TP_SMD_D1.5mm 45.72,16.51 r0 top value=Ã˜1.5mm,SMD
TP11 "Ø1.5mm,SMD" TP_SMD_D1.5mm 23,21.75 r0 top value=Ã˜1.5mm,SMD
TP12 "Ø1.5mm,SMD" TP_SMD_D1.5mm 32.129,22.353 r90 bottom value=Ã˜1.5mm,SMD
TP13 "Ø1.5mm,SMD" TP_SMD_D1.5mm 36.957,24.766 r90 bottom value=Ã˜1.5mm,SMD
TP14 "Ø1.5mm,SMD" TP_SMD_D1.5mm 36.283,20.65 r90 bottom value=Ã˜1.5mm,SMD
TP15 "Ø1.5mm,SMD" TP_SMD_D1.5mm 36.83,29.529 r90 bottom value=Ã˜1.5mm,SMD
TP16 "Ø1.5mm,SMD" TP_SMD_D1.5mm 29.108,15.386 r90 bottom value=Ã˜1.5mm,SMD
TP17 "Ø1.5mm,SMD" TP_SMD_D1.5mm 6.248,36.324 r180 bottom value=Ã˜1.5mm,SMD
TP18 "Ø1.5mm,SMD" TP_SMD_D1.5mm 6.985,25.102 r180 bottom value=Ã˜1.5mm,SMD
TP19 "Ø1.5mm,SMD" TP_SMD_D1.5mm 11.074,33.276 r180 bottom value=Ã˜1.5mm,SMD
TP20 "Ø1.5mm,SMD" TP_SMD_D1.5mm 11.582,30.76 r180 bottom value=Ã˜1.5mm,SMD
TP21 "Ø1.5mm,SMD" TP_SMD_D1.5mm 21.4,10.1 r270 top value=Ã˜1.5mm,SMD
TP22 "Ø1.5mm,SMD" TP_SMD_D1.5mm 2.921,15.718 r90 bottom value=Ã˜1.5mm,SMD
TP23 "Ø1.5mm,SMD" TP_SMD_D1.5mm 24.795,21.38 r90 bottom value=Ã˜1.5mm,SMD
TP24 "TP" TESTPAD-TH 98,60 r0 top
TP25 "Ø1.5mm,SMD" TP_SMD_D1.5mm 8.3,13.7 r270 bottom value=Ã˜1.5mm,SMD
TP26 "Ø1.5mm,SMD" TP_SMD_D1.5mm 8.44,16.51 r270 bottom value=Ã˜1.5mm,SMD
TP27 "Ø1.5mm,SMD" TP_SMD_D1.5mm 6.604,9.399 r270 bottom value=Ã˜1.5mm,SMD
U2 "SKY65943-11" SKY65943-11 134.747,37.465 r270 top
U3 "nRF5340-QKAA" AQFN40P700X700X85_HS-99N 24.925,28.459 r0 top
U4 "GD25WB256E" SON127P800X80_HS-9N 79.187,38.4 r90 top
U5 "PCAL6408A" XQFN40P180X260X50-16N 103.41,32.35 r180 top
U6 "MFFx_M2M_UICC" SON127P600X90_HS-8N 76,14.25 r0 top value="M2M UICC"
U7_S1 "FSA2466UMX" XQFN40P180X260X50-16N 64.8,44.65 r270 top (schematic designator U7)
U7_S2 "FSA2466UMX" XQFN40P180X260X50-16N 51.4,18.5 r270 top (schematic designator U7)
U7_S3 "FSA2466UMX" XQFN40P180X260X50-16N 16.6,27.45 r180 top (schematic designator U7)
U7_S4 "FSA2466UMX" XQFN40P180X260X50-16N 29.9,38.05 r90 top (schematic designator U7)
U7_S5 "FSA2466UMX" XQFN40P180X260X50-16N 103.41,36.209 r0 top (schematic designator U7)
U7_S6 "FSA2466UMX" XQFN40P180X260X50-16N 103.41,27.484 r180 top (schematic designator U7)
U7_S8 "FSA2466UMX" XQFN40P180X260X50-16N 85.2,36.875 r180 top (schematic designator U7)
U7_S10 "FSA2466UMX" XQFN40P180X260X50-16N 58.5,23.25 r0 top (schematic designator U7)
U7_S11 "FSA2466UMX" XQFN40P180X260X50-16N 56.418,44.65 r270 top (schematic designator U7)
U8_S7 "NX3DV2567" XQFN40P180X260X50-16N 99,32.35 r180 top (schematic designator U8)
U8_S9 "NX3DV2567" XQFN40P180X260X50-16N 88.1,18.05 r0 top (schematic designator U8)
U9 "nPM1300-QEAA" Nordic_QFN50P500X500X90-33N 13.2,14.9 r180 top
X1 "32MHz" BT-XTAL_2016 32.05,32.313 r90 top
Y1 "Shunt 2.54mm" Shunt_2.54mm_Horizontal 3.485,49.859 r270 top
Y2 "Shunt 2.54mm" Shunt_2.54mm_Horizontal 103.41,3.494 r0 top

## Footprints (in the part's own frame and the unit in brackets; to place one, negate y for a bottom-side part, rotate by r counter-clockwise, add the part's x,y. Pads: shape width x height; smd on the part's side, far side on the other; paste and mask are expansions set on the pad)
AQFN40P700X700X85_HS-99N [mm] "AQFN, 98-Leads, Body 7.00x7.00mm, Pitch 0.40mm, Thermal Pad 5.4x5.0mm, IPC Medium Density"
  rect 5.4x5 smd paste-5 mask+0.05: 104(0.2,0)
  round 0.4 smd paste+0.012 mask+0.05: A1(-3.2,3.2) A31(3.2,3.2) AL1(-3.2,-3.2) AL31(3.2,-3.2)
  round 0.225 smd paste+0.012 mask+0.05: A5(-2.2,3.2) A13(-0.6,3.2) A15(-0.2,3.2) A17(0.2,3.2) A19(0.6,3.2) A21(1,3.2) A23(1.4,3.2) A25(1.8,3.2) A27(2.2,3.2) AA1(-3.2,-1) AA31(3.2,-1) AB2(-2.8,-1.2) AC1(-3.2,-1.4) AC31(3.2,-1.4) AD2(-2.8,-1.6) AE1(-3.2,-1.8) AE31(3.2,-1.8) AF2(-2.8,-2) AG1(-3.2,-2.2) AG31(3.2,-2.2) AH2(-2.8,-2.4) AJ1(-3.2,-2.6) AJ31(3.2,-2.6) AK2(-2.8,-2.8) AK4(-2.4,-2.8) AK6(-2,-2.8) AK8(-1.6,-2.8) AK10(-1.2,-2.8) AK12(-0.8,-2.8) AK14(-0.4,-2.8) AK16(0,-2.8) AK18(0.4,-2.8) AK20(0.8,-2.8) AK22(1.2,-2.8) AK24(1.6,-2.8) AK26(2,-2.8) AK28(2.4,-2.8) AK30(2.8,-2.8) AL3(-2.6,-3.2) AL5(-2.2,-3.2) AL7(-1.8,-3.2) AL9(-1.4,-3.2) AL11(-1,-3.2) AL13(-0.6,-3.2) AL15(-0.2,-3.2) AL17(0.2,-3.2) AL19(0.6,-3.2) AL21(1,-3.2) AL23(1.4,-3.2) AL25(1.8,-3.2) AL27(2.2,-3.2) AL29(2.6,-3.2) B2(-2.8,2.8) B4(-2.4,2.8) B6(-2,2.8) B8(-1.6,2.8) B10(-1.2,2.8) B12(-0.8,2.8) B14(-0.4,2.8) B16(0,2.8) B18(0.4,2.8) B20(0.8,2.8) B22(1.2,2.8) B24(1.6,2.8) B26(2,2.8) B28(2.4,2.8) B30(2.8,2.8) C1(-3.2,2.6) C31(3.2,2.6) D2(-2.8,2.4) E1(-3.2,2.2) E31(3.2,2.2) F2(-2.8,2) G1(-3.2,1.8) G31(3.2,1.8) H2(-2.8,1.6) J1(-3.2,1.4) J31(3.2,1.4) K2(-2.8,1.2) L1(-3.2,1) L31(3.2,1) M2(-2.8,0.8) N1(-3.2,0.6) N31(3.2,0.6) P2(-2.8,0.4) R1(-3.2,0.2) R31(3.2,0.2) T2(-2.8,0) U1(-3.2,-0.2) U31(3.2,-0.2) V2(-2.8,-0.4) W1(-3.2,-0.6) W31(3.2,-0.6) Y2(-2.8,-0.8)
  rrect15% 1.1x1 on Top Paste: ""(-1.75,-1.8) ""(-1.75,-0.6) ""(-1.75,0.6) ""(-1.75,1.8) ""(-0.45,-1.8) ""(-0.45,-0.6) ""(-0.45,0.6) ""(-0.45,1.8) ""(0.85,-1.8) ""(0.85,-0.6) ""(0.85,0.6) ""(0.85,1.8) ""(2.15,-1.8) ""(2.15,-0.6) ""(2.15,0.6) ""(2.15,1.8)
  silkscreen extent -4.22,3.23 -3.97,3.47, body extent -3.5,-3.5 3.5,3.5, height 0.85
BT-XTAL_2016 [mm] "Crystal 2.0 x 1.6 mm"
  rect 0.95x0.85 smd: 1(-0.725,-0.575) 2(0.725,-0.575) 3(0.725,0.575) 4(-0.725,0.575)
  body extent -1.05,-0.85 1.05,0.85, height 0.56
CAPC0603X03L_C [mm] "Chip Capacitor, 2-Leads, Body 0.6x0.3mm, IPC High Density"
  rect 0.27x0.3 smd mask+0.05: 1(-0.285,0) 2(0.285,0)
  body extent -0.3,-0.15 0.31,0.15, height 0.3
CAPC0603X03L_C_NC [mm] "Chip Capacitor, 2-Leads, Body 0.6x0.3mm, IPC High Density"
  rect 0.27x0.3 smd mask+0.05: 1(-0.285,0) 2(0.285,0)
CAPC1005X04L [mm] "Chip Capacitor, 2-Leads, Body 1.0x0.5mm, IPC High Density"
  rect 0.6x0.5 smd: 1(-0.5,0) 2(0.5,0)
  body extent -0.51,-0.25 0.51,0.25, height 0.5
CAPC1005X04L_NC [mm] "Chip Capacitor, 2-Leads, Body 1.0x0.5mm, IPC High Density"
  rect 0.6x0.5 smd: 1(-0.5,0) 2(0.5,0)
CAPC1608X06L [mm] "Chip Capacitor, 2-Leads, Body 1.6x0.8mm, IPC High Density"
  rect 0.75x0.8 smd: 1(-0.675,0) 2(0.675,0)
  silkscreen extent -1.17,-0.5 1.17,0.5, body extent -0.8,-0.43 0.8,0.43, height 0.8
"COAXIAL RF U.FL-R-SMT-1" [mm]
  rect 1x1.05 smd: 1(0,-1.525)
  rect 1.05x2.2 smd: 2(-1.475,0) 2(1.475,0)
  Top Layer pour cut-out: 0.85,1.3 -0.85,1.3 -0.85,-1.525 0.85,-1.525
  silkscreen extent -0.62,-0.62 0.62,1.3, body extent -1.5,-1.6 1.5,1.5, height 1.25
COAXIAL-SWF [mm]
  rect 0.5x0.58 smd: 1(0,1.16) 3(0,-1.16)
  rect 0.75x0.8 smd: 2(-1.025,-0.95) 2(-1.025,0.95) 2(1.025,-0.95) 2(1.025,0.95)
  Top Layer pour cut-out: -0.65,0.55 0.65,0.55 0.65,1.35 -0.65,1.35
  Top Layer pour cut-out: 0.65,-0.55 -0.65,-0.55 -0.65,-1.35 0.65,-1.35
  silkscreen extent -1.25,-0.22 1.25,0.22, body extent -1.26,-1.3 1.26,1.3, height 1.55
DFN65P100X40-3L [mm] "DFN, 3-Leads, Body 0.60x1.00mm, Pitch 0.65mm, IPC High Density"
  rect 0.4x0.25 smd mask+0.05: 1(-0.35,0.225) 2(-0.35,-0.225)
  rect 0.4x0.7 smd mask+0.065: 3(0.35,0)
  body extent -0.53,-0.33 0.53,0.33, height 0.4
DFN65P200X200X80_HS-6N [mm] "DFN, 6-Leads, Body 2.00x2.00mm, Pitch 0.65mm, IPC Medium Density"
  rect 0.45x0.42 smd mask+0.055: 1(-0.905,0.65) 2(-0.905,0) 3(-0.905,-0.65) 4(0.905,-0.65) 5(0.905,0) 6(0.905,0.65)
  rect 0.92x0.71 smd mask+0.055: 3(0,-0.475) 6(0,0.475)
  body extent -1.05,-1.05 1.05,1.05, height 0.65
DSGP.1575.18.4.C.02 [mm]
  rect 2x2.5 smd paste-0.25 mask+0.3: 1(0,-8.55)
  rect 3.5x3.5 smd paste-0.6 mask+0.1: 2(-6.75,-6.75) 2(-6.75,0) 2(-6.75,6.75) 2(0,6.75) 2(0,0) 2(6.75,-6.75) 2(6.75,0) 2(6.75,6.75)
  Keep-Out Layer lines w0.01: -1.26,-10.14 -1.84,-10.14 -1.84,-6.96 1.84,-6.96 1.84,-10.14 1.26,-10.14
  Multi-Layer pour cut-out: -2,-6.8 -2,-10.3 2,-10.3 2,-6.8
  silkscreen extent -9,-9 9,9, body extent -9,-9.01 9,9, height 4.02
Fiducial [mm] "Fiducial Mark"
  round 1 smd far side paste+0 mask+0.5: 0(0,0)
  round 1 smd paste+0 mask+0.5: 0(0,0)
  Top Layer keep-out circle w0.01: c0,0 r1
  Bottom Layer keep-out circle w0.01: c0,0 r1
HDR_2x3-SMD [mil] "Board-Board Conn, Header, 6-way, 2-row"
  rect 40x113 smd: 1(-100,-100) 2(-100,100) 3(0,-100) 4(0,100) 5(100,-100) 6(100,100)
  silkscreen extent -160,-140 150,100, body extent -150,-148 150,148, height 382
HDR_2x5-SMD-1.27mm [mm] "Pin Header, 1.27mm SMD"
  rect 0.76x2.4 smd: 1(-2.54,-1.95) 2(-2.54,1.95) 3(-1.27,-1.95) 4(-1.27,1.95) 5(0,-1.95) 6(0,1.95) 7(1.27,-1.95) 8(1.27,1.95) 9(2.54,-1.95) 10(2.54,1.95)
  silkscreen extent -3.17,-0.35 3.17,0.35, body extent -3.16,-2.92 3.19,2.92, height 5.96
HDR_2x5-SMD-1.27mm-K [mm] "SMT MICRO HEADER, (1,27) .050\" Keying Shroud"
  rect 0.76x2.4 smd: 1(-2.54,-1.95) 2(-2.54,1.95) 3(-1.27,-1.95) 4(-1.27,1.95) 5(0,-1.95) 6(0,1.95) 7(1.27,-1.95) 8(1.27,1.95) 9(2.54,-1.95) 10(2.54,1.95)
  silkscreen extent -3.17,-0.35 3.17,0.35, body extent -3.14,-2.92 3.14,2.92, height 6.11
HDR_2x6-NC [mm] "Pin Header, 2.54mm through hole"
  rect 1.5x1.5 hole 0.9: 1(-6.35,-1.27)
  round 1.5 hole 0.9: 2(-6.35,1.27) 3(-3.81,-1.27) 4(-3.81,1.27) 5(-1.27,-1.27) 6(-1.27,1.27) 7(1.27,-1.27) 8(1.27,1.27) 9(3.81,-1.27) 10(3.81,1.27) 11(6.35,-1.27) 12(6.35,1.27)
  silkscreen extent -7.62,-2.41 7.62,2.54
HDR_2x8-NC [mm] "Pin Header, 2.54mm through hole"
  rect 1.5x1.5 hole 0.9: 1(-8.89,-1.27)
  round 1.5 hole 0.9: 2(-8.89,1.27) 3(-6.35,-1.27) 4(-6.35,1.27) 5(-3.81,-1.27) 6(-3.81,1.27) 7(-1.27,-1.27) 8(-1.27,1.27) 9(1.27,-1.27) 10(1.27,1.27) 11(3.81,-1.27) 12(3.81,1.27) 13(6.35,-1.27) 14(6.35,1.27) 15(8.89,-1.27) 16(8.89,1.27)
  silkscreen extent -10.16,-2.41 10.16,2.54
HDR_2x10-NC [mm] "Pin Header, 2.54mm through hole"
  rect 1.5x1.5 hole 0.9: 1(-11.43,-1.27)
  round 1.5 hole 0.9: 2(-11.43,1.27) 3(-8.89,-1.27) 4(-8.89,1.27) 5(-6.35,-1.27) 6(-6.35,1.27) 7(-3.81,-1.27) 8(-3.81,1.27) 9(-1.27,-1.27) 10(-1.27,1.27) 11(1.27,-1.27) 12(1.27,1.27) 13(3.81,-1.27) 14(3.81,1.27) 15(6.35,-1.27) 16(6.35,1.27) 17(8.89,-1.27) 18(8.89,1.27) 19(11.43,-1.27) 20(11.43,1.27)
  silkscreen extent -12.7,-2.41 12.7,2.54
HDR_2x10-SMD-1.27mm-K-SWD [mm] "SMT MICRO HEADER, (1,27) .050\" Keying Shroud w/ pin 7 removed"
  rect 0.76x2.4 smd: 1(-5.715,-1.95) 2(-5.715,1.95) 3(-4.445,-1.95) 4(-4.445,1.95) 5(-3.175,-1.95) 6(-3.175,1.95) 8(-1.905,1.95) 9(-0.635,-1.95) 10(-0.635,1.95) 11(0.635,-1.95) 12(0.635,1.95) 13(1.905,-1.95) 14(1.905,1.95) 15(3.175,-1.95) 16(3.175,1.95) 17(4.445,-1.95) 18(4.445,1.95) 19(5.715,-1.95) 20(5.715,1.95)
  silkscreen extent -6.35,-3.15 6.35,0.35, body extent -6.35,-2.92 6.35,2.92, height 6.11
INDC0603X03L_C [mm] "Chip Inductor, 2-Leads, Body 0.6x0.3mm, IPC High Density"
  rect 0.27x0.3 smd: 1(-0.285,0) 2(0.285,0)
  body extent -0.31,-0.16 0.31,0.16, height 0.26
INDC1005X04L [mm] "Chip Inductor, 2-Leads, Body 1.0x0.5mm, IPC High Density"
  rect 0.65x0.5 smd: 1(-0.475,0) 2(0.475,0)
  body extent -0.5,-0.28 0.5,0.33, height 0.5
INDC1005X04L_NC [mm] "Chip Inductor, 2-Leads, Body 1.0x0.5mm, IPC High Density"
  rect 0.65x0.5 smd: 1(-0.475,0) 2(0.475,0)
INDC1005X04L_WW [mm] "Chip Inductor, 2-Leads, Body 1.0x0.5mm, IPC High Density"
  rect 0.65x0.5 smd: 1(-0.475,0) 2(0.475,0)
  body extent -0.5,-0.3 0.5,0.3, height 0.51
INDC1608X06L [mm] "Chip Inductor, 2-Leads, Body 1.6x0.8mm, IPC High Density"
  rect 0.75x0.8 smd: 1(-0.675,0) 2(0.675,0)
  silkscreen extent -1.17,-0.5 1.17,0.5, body extent -0.8,-0.48 0.8,0.48, height 0.8
INDC2016X10N [mm] "Chip Inductor, 2-Leads, Body 2.00x1.60mm, IPC Medium Density"
  rect 1.13x1.82 smd: 1(-0.885,0) 2(0.885,0)
  body extent -1.1,-0.9 1.1,0.9, height 1
JS102011JAQN [mm] "Slide Switches - DPDT, SMD, ON-ON"
  round 0.9 hole 0.9 unplated mask+0: 0(-3.4,0) 0(3.4,0)
  rect 0.5x0.5 smd: 1(-2.5,-1.2) 3(2.5,-1.2) 4(-2.5,1.2) 6(2.5,1.2)
  rect 1x1.6 smd: 2(0,-1.2) 5(0,1.2)
  Top Layer region: -3,0.562 -2.838,0.4 -2,0.4 -2,2 -3,2
  Top Layer region: -3,-0.562 -2.838,-0.4 -2,-0.4 -2,-2 -3,-2
  Top Layer region: 3,0.562 2.838,0.4 2,0.4 2,2 3,2
  Top Layer region: 3,-0.562 2.838,-0.4 2,-0.4 2,-2 3,-2
  silkscreen extent -4.5,-3.8 4.5,1.75, body extent -4.25,-3.75 4.25,1.75, height 3.5
KLS1-SIM-066 [mm]
  rect 0.7x2.1 smd: 0(-1.67,-13.55) 0(-1.67,-1.55) 0(11.32,-13.55) 0(11.32,-1.55)
  rect 0.75x1.2 smd: C1(5.08,0) C2(2.54,0) C3(0,0) C5(6.35,0) C6(3.81,0) C7(1.27,0)
  rect 0.65x1.2 smd: CD(7.3,0)
  round 0.75 hole 0.75 unplated: ""(-0.17,-12.3) ""(8.33,-12.3)
  Top Layer keep-out region: 6.83,-13.4 5.63,-13.4 5.63,-9.6 6.83,-9.6
  Top Layer keep-out region: 4.29,-13.4 3.09,-13.4 3.09,-9.6 4.29,-9.6
  Top Layer keep-out region: 1.75,-13.4 0.55,-13.4 0.55,-9.6 1.75,-9.6
  Top Layer keep-out region: 6.83,-6.5 5.63,-6.5 5.63,-2.7 6.83,-2.7
  Top Layer keep-out region: 4.29,-6.5 3.09,-6.5 3.09,-2.7 4.29,-2.7
  Top Layer keep-out region: 1.75,-6.5 0.55,-6.5 0.55,-2.7 1.75,-2.7
  silkscreen extent -1.38,-14.3 11.02,-0.7, body extent -1.72,-14.49 11.37,0.09, height 1.44
L-KLS7-TS6616B-2.5-160-T [mm] "6.2Ã—6.4mm TACT Switch, without ground connector"
  rect 2.75x1.4 smd: 1(-3.025,2) 1(3.025,2) 2(-3.025,-2) 2(3.025,-2)
  silkscreen extent -3,-3 3,3, body extent -3.6,-3.1 3.6,3.1, height 2.5
LabelSilk_15x40 [mm] "PCA version label, stick-on, 15x40mm"
  silkscreen extent 0,0 40,15, body extent 0,0 40,15, height 0.05
LED_0603_G [mil] "SMD Super Bright LED, GREEN"
  rect 30x32 smd: 1(-27.5,0) 2(27.5,0)
  silkscreen extent -58,-10 -58,10, body extent -32,-16 32,16, height 24
LGA50P1210X1110X130-113N [mm]
  rect 0.7x0.45 smd paste-2539.97 mask-5: 1(-5,-5.625)
  rect 0.3x0.45 smd mask+0.05: 2(-4.25,-5.625) 3(-3.75,-5.625) 4(-3.25,-5.625) 5(-2.75,-5.625) 6(-2.25,-5.625) 7(-1.75,-5.625) 8(-1.25,-5.625) 9(-0.75,-5.625) 10(-0.25,-5.625) 11(0.25,-5.625) 12(0.75,-5.625) 13(1.25,-5.625) 14(1.75,-5.625) 15(2.25,-5.625) 16(2.75,-5.625) 17(3.25,-5.625) 18(3.75,-5.625) 19(4.25,-5.625) 42(4.25,5.625) 43(3.75,5.625) 44(3.25,5.625) 45(2.75,5.625) 46(2.25,5.625) 47(1.75,5.625) 48(1.25,5.625) 49(0.75,5.625) 50(0.25,5.625) 51(-0.25,5.625) 52(-0.75,5.625) 53(-1.25,5.625) 54(-1.75,5.625) 55(-2.25,5.625) 56(-2.75,5.625) 57(-3.25,5.625) 58(-3.75,5.625) 59(-4.25,5.625)
  rect 0.7x0.7 smd mask+0.05: 20(5,-5.5) 41(5,5.5) 60(-5,5.5)
  rect 0.45x0.3 smd mask+0.05: 21(5.125,-4.75) 22(5.125,-4.25) 23(5.125,-3.75) 24(5.125,-3.25) 25(5.125,-2.75) 26(5.125,-2.25) 27(5.125,-1.75) 28(5.125,-1.25) 29(5.125,-0.75) 30(5.125,-0.25) 31(5.125,0.25) 32(5.125,0.75) 33(5.125,1.25) 34(5.125,1.75) 35(5.125,2.25) 36(5.125,2.75) 37(5.125,3.25) 38(5.125,3.75) 39(5.125,4.25) 40(5.125,4.75) 61(-5.125,4.75) 62(-5.125,4.25) 63(-5.125,3.75) 64(-5.125,3.25) 65(-5.125,2.75) 66(-5.125,2.25) 67(-5.125,1.75) 68(-5.125,1.25) 69(-5.125,0.75) 70(-5.125,0.25) 71(-5.125,-0.25) 72(-5.125,-0.75) 73(-5.125,-1.25) 74(-5.125,-1.75) 75(-5.125,-2.25) 76(-5.125,-2.75) 77(-5.125,-3.25) 78(-5.125,-3.75) 79(-5.125,-4.25) 80(-5.125,-4.75)
  rect 0.3x0.3 smd mask+0.05: 81(-3.4,-4.1) 82(-2.85,-4.1) 83(-2.3,-4.1) 84(-0.55,-4.1) 85(0,-4.1) 86(0.55,-4.1) 87(2.3,-4.1) 88(2.85,-4.1) 89(3.4,-4.1) 90(2.15,-0.55) 91(2.15,0) 92(2.15,0.55) 93(3.4,4.1) 94(2.85,4.1) 95(2.3,4.1) 96(0.55,4.1) 97(0,4.1) 98(-0.55,4.1) 99(-2.3,4.1) 100(-2.85,4.1) 101(-3.4,4.1) 102(-2.15,0.55) 103(-2.15,0) 104(-2.15,-0.55)
  rect 1.6x1.6 smd mask+0.05: 105(-2.85,-2.85) 106(0,-2.85) 107(2.85,-2.85) 109(2.85,2.85) 110(0,2.85) 111(-2.85,2.85) 113(0,0)
  rect 1.95x1.6 smd mask+0.05: 108(3.575,0) 112(-3.575,0)
  Top Layer region: -5.35,-5.15 -5.35,-5.85 -4.65,-5.85 -4.65,-5.4 -4.9,-5.15
  silkscreen extent -5.99,-6.5 -5.69,-6.2, body extent -5.6,-6.1 5.6,6.1, height 1.21
LIST_1x6_SMD-NC [mm] "Pin List, 2.54mm, SMD"
  rect 1.02x2.19 smd: 1(0,-1.465) 1(0,1.465) 2(2.54,-1.465) 2(2.54,1.465) 3(5.08,-1.465) 3(5.08,1.465) 4(7.62,-1.465) 4(7.62,1.465) 5(10.16,-1.465) 5(10.16,1.465) 6(12.7,-1.465) 6(12.7,1.465)
  silkscreen extent -1.27,-1.27 13.97,1.27
LIST_1x8_SMD-NC [mm] "Pin List, 2.54mm, SMD"
  rect 1.02x2.19 smd: 1(0,-1.465) 1(0,1.465) 2(2.54,-1.465) 2(2.54,1.465) 3(5.08,-1.465) 3(5.08,1.465) 4(7.62,-1.465) 4(7.62,1.465) 5(10.16,-1.465) 5(10.16,1.465) 6(12.7,-1.465) 6(12.7,1.465) 7(15.24,-1.465) 7(15.24,1.465) 8(17.78,-1.465) 8(17.78,1.465)
  silkscreen extent -1.27,-1.27 19.05,1.27
LIST_1x10_SMD-NC [mm] "Pin List, 2.54mm, SMD"
  rect 1.02x2.19 smd: 1(0,-1.465) 1(0,1.465) 2(2.54,-1.465) 2(2.54,1.465) 3(5.08,-1.465) 3(5.08,1.465) 4(7.62,-1.465) 4(7.62,1.465) 5(10.16,-1.465) 5(10.16,1.465) 6(12.7,-1.465) 6(12.7,1.465) 7(15.24,-1.465) 7(15.24,1.465) 8(17.78,-1.465) 8(17.78,1.465) 9(20.32,-1.465) 9(20.32,1.465) 10(22.86,-1.465) 10(22.86,1.465)
  silkscreen extent -1.27,-1.27 24.13,1.27
LIST_1x13_SMD [mm] "Pin List, 2.54mm, SMD"
  rect 1.02x2.19 smd: 1(0,-1.465) 1(0,1.465) 2(2.54,-1.465) 2(2.54,1.465) 3(5.08,-1.465) 3(5.08,1.465) 4(7.62,-1.465) 4(7.62,1.465) 5(10.16,-1.465) 5(10.16,1.465) 6(12.7,-1.465) 6(12.7,1.465) 7(15.24,-1.465) 7(15.24,1.465) 8(17.78,-1.465) 8(17.78,1.465) 9(20.32,-1.465) 9(20.32,1.465) 10(22.86,-1.465) 10(22.86,1.465) 11(25.4,-1.465) 11(25.4,1.465) 12(27.94,-1.465) 12(27.94,1.465) 13(30.48,-1.465) 13(30.48,1.465)
  silkscreen extent -1.27,-1.27 31.75,1.27, body extent -1.27,-2.5 31.75,2.5, height 9.82
LIST_1x13_SMD-NC [mm] "Pin List, 2.54mm, SMD"
  rect 1.02x2.19 smd: 1(0,-1.465) 1(0,1.465) 2(2.54,-1.465) 2(2.54,1.465) 3(5.08,-1.465) 3(5.08,1.465) 4(7.62,-1.465) 4(7.62,1.465) 5(10.16,-1.465) 5(10.16,1.465) 6(12.7,-1.465) 6(12.7,1.465) 7(15.24,-1.465) 7(15.24,1.465) 8(17.78,-1.465) 8(17.78,1.465) 9(20.32,-1.465) 9(20.32,1.465) 10(22.86,-1.465) 10(22.86,1.465) 11(25.4,-1.465) 11(25.4,1.465) 12(27.94,-1.465) 12(27.94,1.465) 13(30.48,-1.465) 13(30.48,1.465)
  silkscreen extent -1.27,-1.27 31.75,1.27
LIST_ANG_1x2-SMD-2.54MM [mm] "Pin List, 2.54mm, Surface Mount, Angled"
  round 1.78 hole 1.78 unplated: 0(0,-4.496)
  rect 1.27x3.18 smd: 1(-1.27,0) 2(1.27,0)
  silkscreen extent -2.54,-11.58 2.54,-1.92, body extent -2.56,-11.61 2.52,1.35, height 3.03
LIST_ANG_1x4-SMD-2.54MM [mm] "Pin List, 2.54mm, Surface Mount, Angled"
  round 1.78 hole 1.78 unplated: 0(-2.54,-4.496) 0(2.54,-4.496)
  rect 1.27x3.18 smd: 1(-3.81,0) 2(-1.27,0) 3(1.27,0) 4(3.81,0)
  silkscreen extent -5.08,-11.58 5.08,-1.92, body extent -5.1,-11.61 5.06,1.35, height 3.03
LIST_ANG_1x6-SMD-2.54MM [mm] "Pin List, 2.54mm, Surface Mount, Angled"
  round 1.78 hole 1.78 unplated: 0(-5.08,-4.496) 0(5.08,-4.496)
  rect 1.27x3.18 smd: 1(-6.35,0) 2(-3.81,0) 3(-1.27,0) 4(1.27,0) 5(3.81,0) 6(6.35,0)
  silkscreen extent -6.6,-9.74 6.73,2.79, body extent -7.64,-11.61 7.6,1.35, height 3.03
Molex_502774-0891 [mm] "SD Micro, Molex 0473521001, Push-Push"
  rect 1.5x1.7 smd mask+0.05: 0(-0.75,14.77) 0(12.75,14.77)
  rect 1.6x1.5 smd mask+0.05: 0(-0.21,0)
  rect 1.7x1.5 smd mask+0.05: 0(12.45,0)
  rect 0.8x1.68 smd mask+0.05: 1(8.9,0.08) 2(7.8,0.08) 3(6.7,0.08) 4(5.6,0.08) 5(4.5,0.08) 6(3.4,0.08) 7(2.3,0.08) 8(1.2,0.08)
  rect 1.29x1.3 smd mask+0.05: 9(-0.96,1.6)
  rect 1.29x1.4 smd mask+0.05: 10(-0.96,8.97)
  silkscreen extent -1.2,0 13,15, body extent -1.2,-0.61 13.1,15.39, height 1.78
NORDIC_LOGO_LYING [mm]
  silkscreen extent -2.57,-2.24 13.7,2.24
Nordic_QFN50P500X500X90-33N [mm] "QFN32 5x5x0.85mm, 0.5mm pitch - Medium Density"
  oval 0.85x0.3 smd: 1(-2.45,1.75) 2(-2.45,1.25) 3(-2.45,0.75) 4(-2.45,0.25) 5(-2.45,-0.25) 6(-2.45,-0.75) 7(-2.45,-1.25) 8(-2.45,-1.75) 17(2.45,-1.75) 18(2.45,-1.25) 19(2.45,-0.75) 20(2.45,-0.25) 21(2.45,0.25) 22(2.45,0.75) 23(2.45,1.25) 24(2.45,1.75)
  oval 0.3x0.85 smd: 9(-1.75,-2.45) 10(-1.25,-2.45) 11(-0.75,-2.45) 12(-0.25,-2.45) 13(0.25,-2.45) 14(0.75,-2.45) 15(1.25,-2.45) 16(1.75,-2.45) 25(1.75,2.45) 26(1.25,2.45) 27(0.75,2.45) 28(0.25,2.45) 29(-0.25,2.45) 30(-0.75,2.45) 31(-1.25,2.45) 32(-1.75,2.45)
  rect 3.5x3.5 smd: 33(0,0)
  silkscreen extent -3.43,-2.57 2.57,2.62, body extent -2.5,-2.5 2.5,2.5, height 0.9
